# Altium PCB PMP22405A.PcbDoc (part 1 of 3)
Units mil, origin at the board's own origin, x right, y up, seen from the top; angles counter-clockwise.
Board outline 4300 x 4000 mil, 6 copper layers (Top Layer, Layer 2, Signal Layer 3, Signal Layer 4, Layer 5, Bottom Layer), stack 61.712 mil thick; 195 components, 65 nets, 472 pads, 772 vias.
Unrouted connection lines stored in the file: 12.
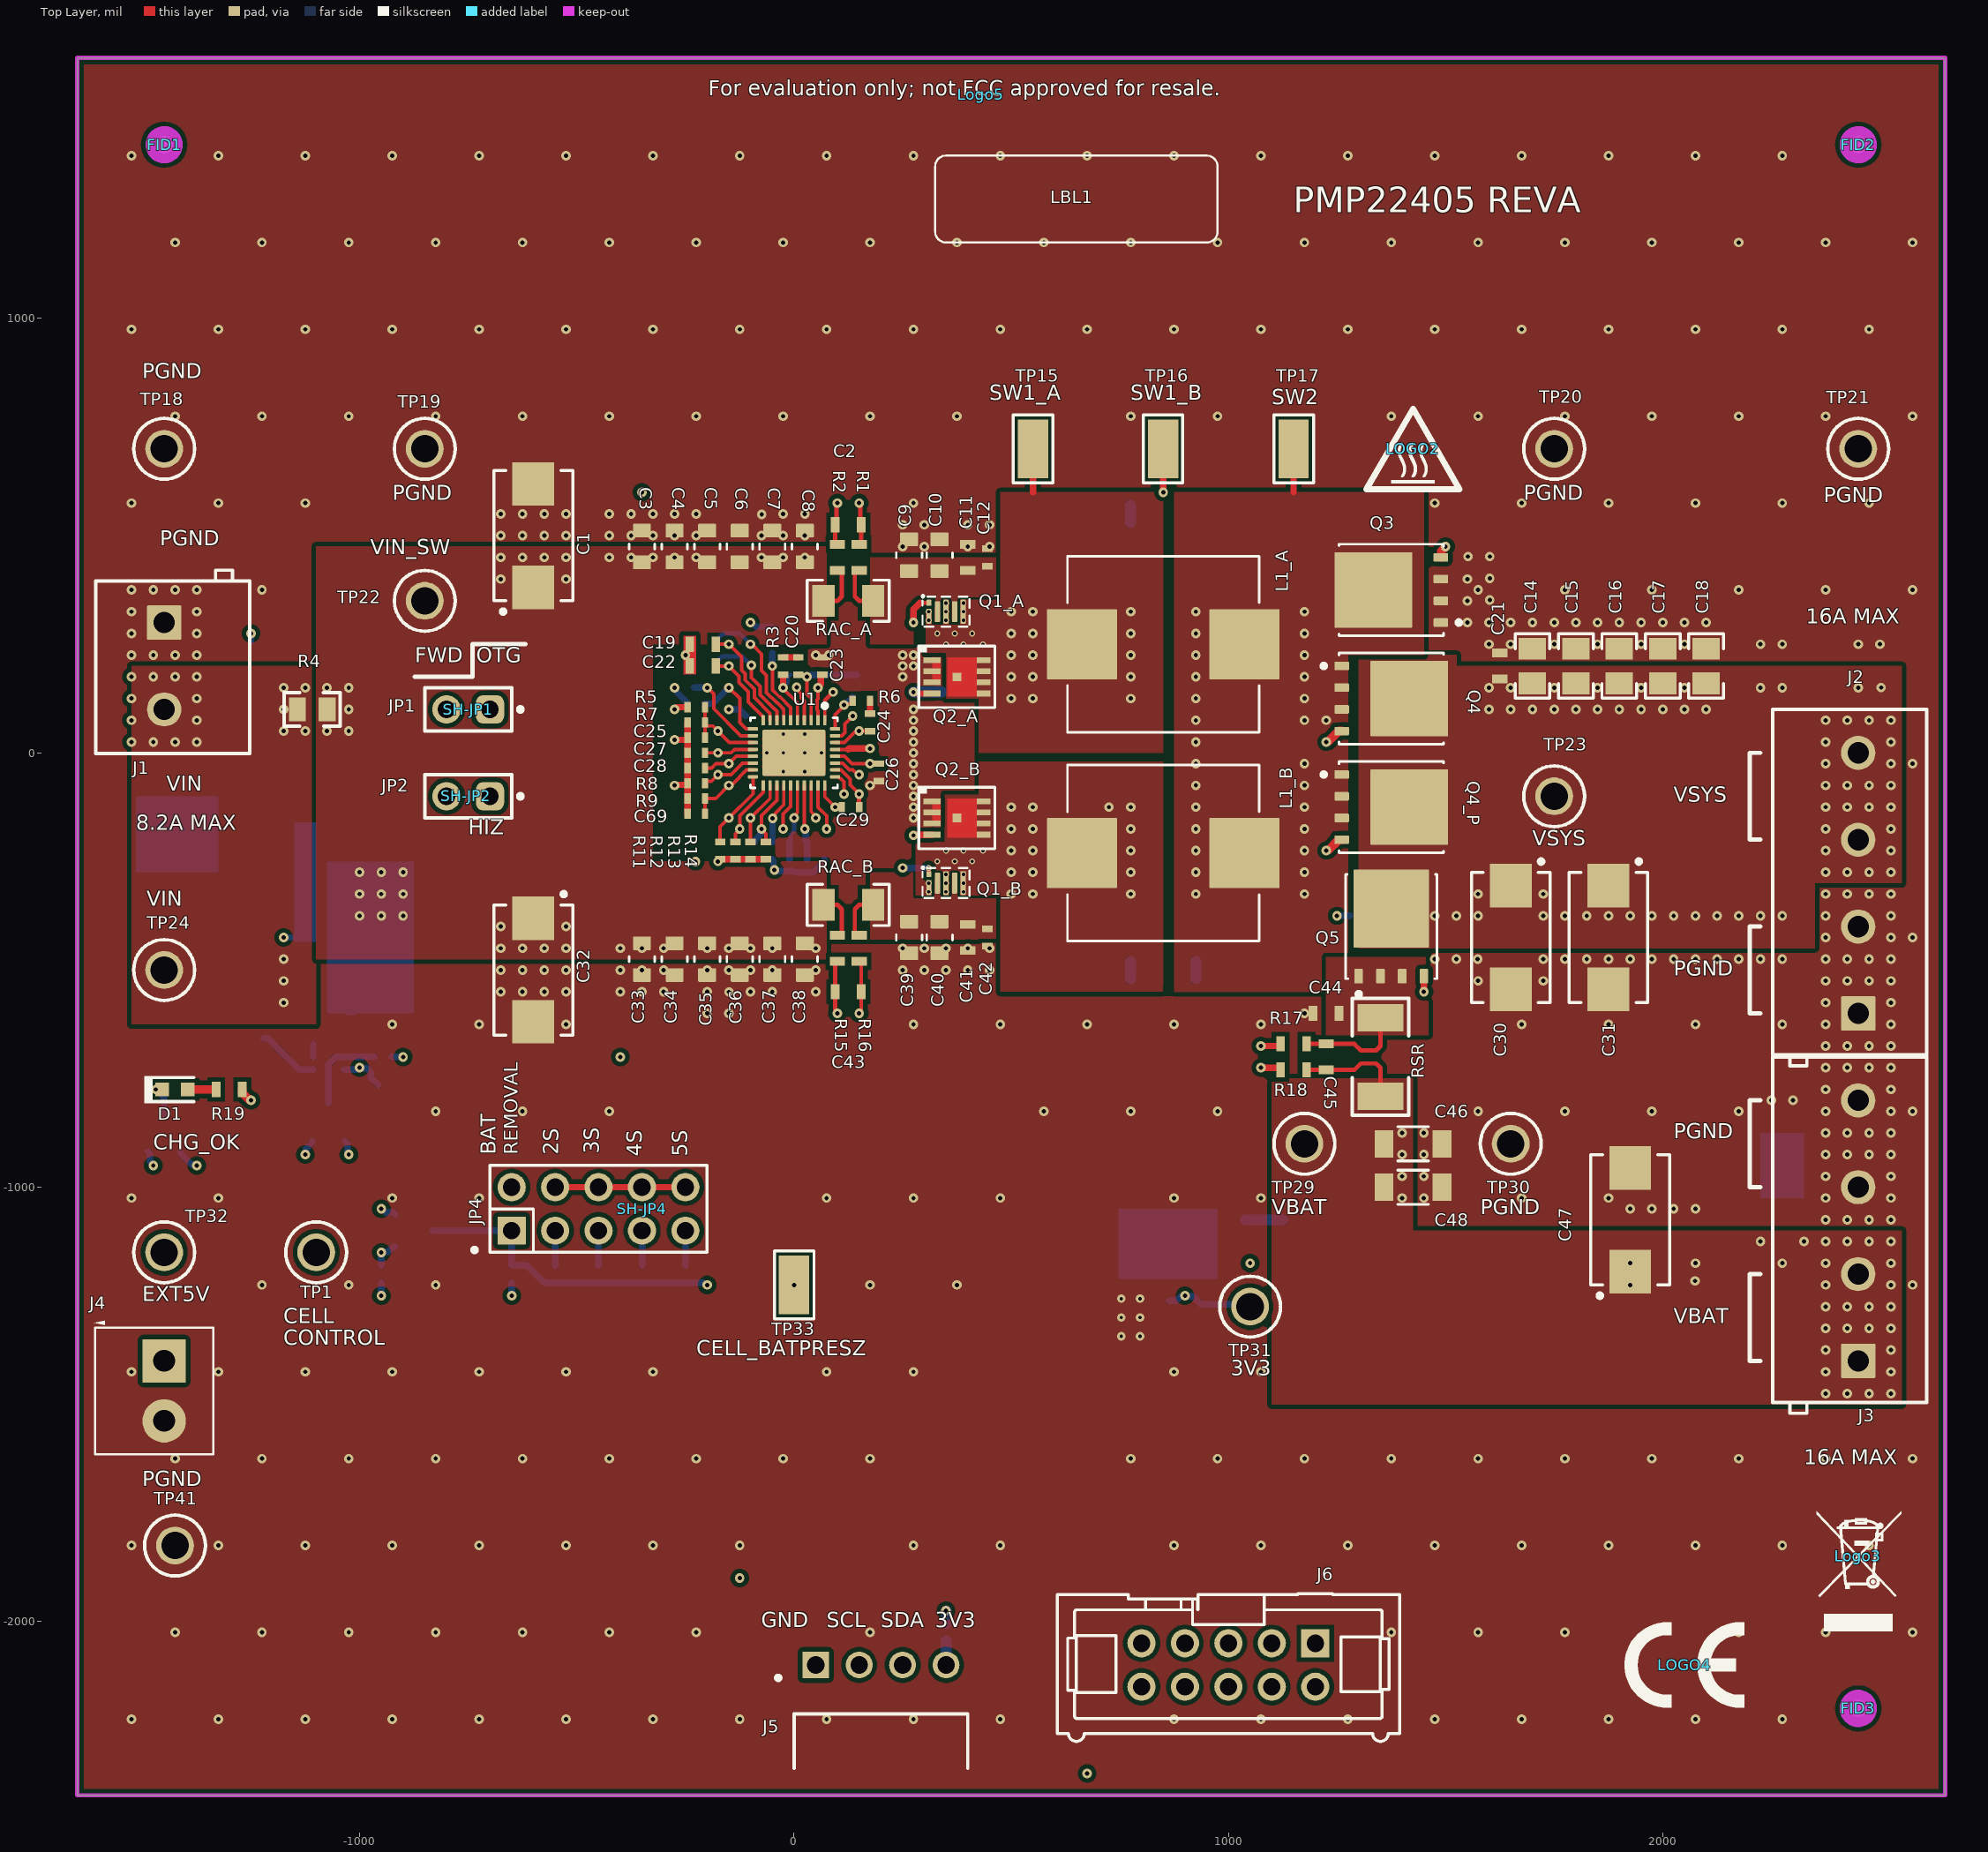
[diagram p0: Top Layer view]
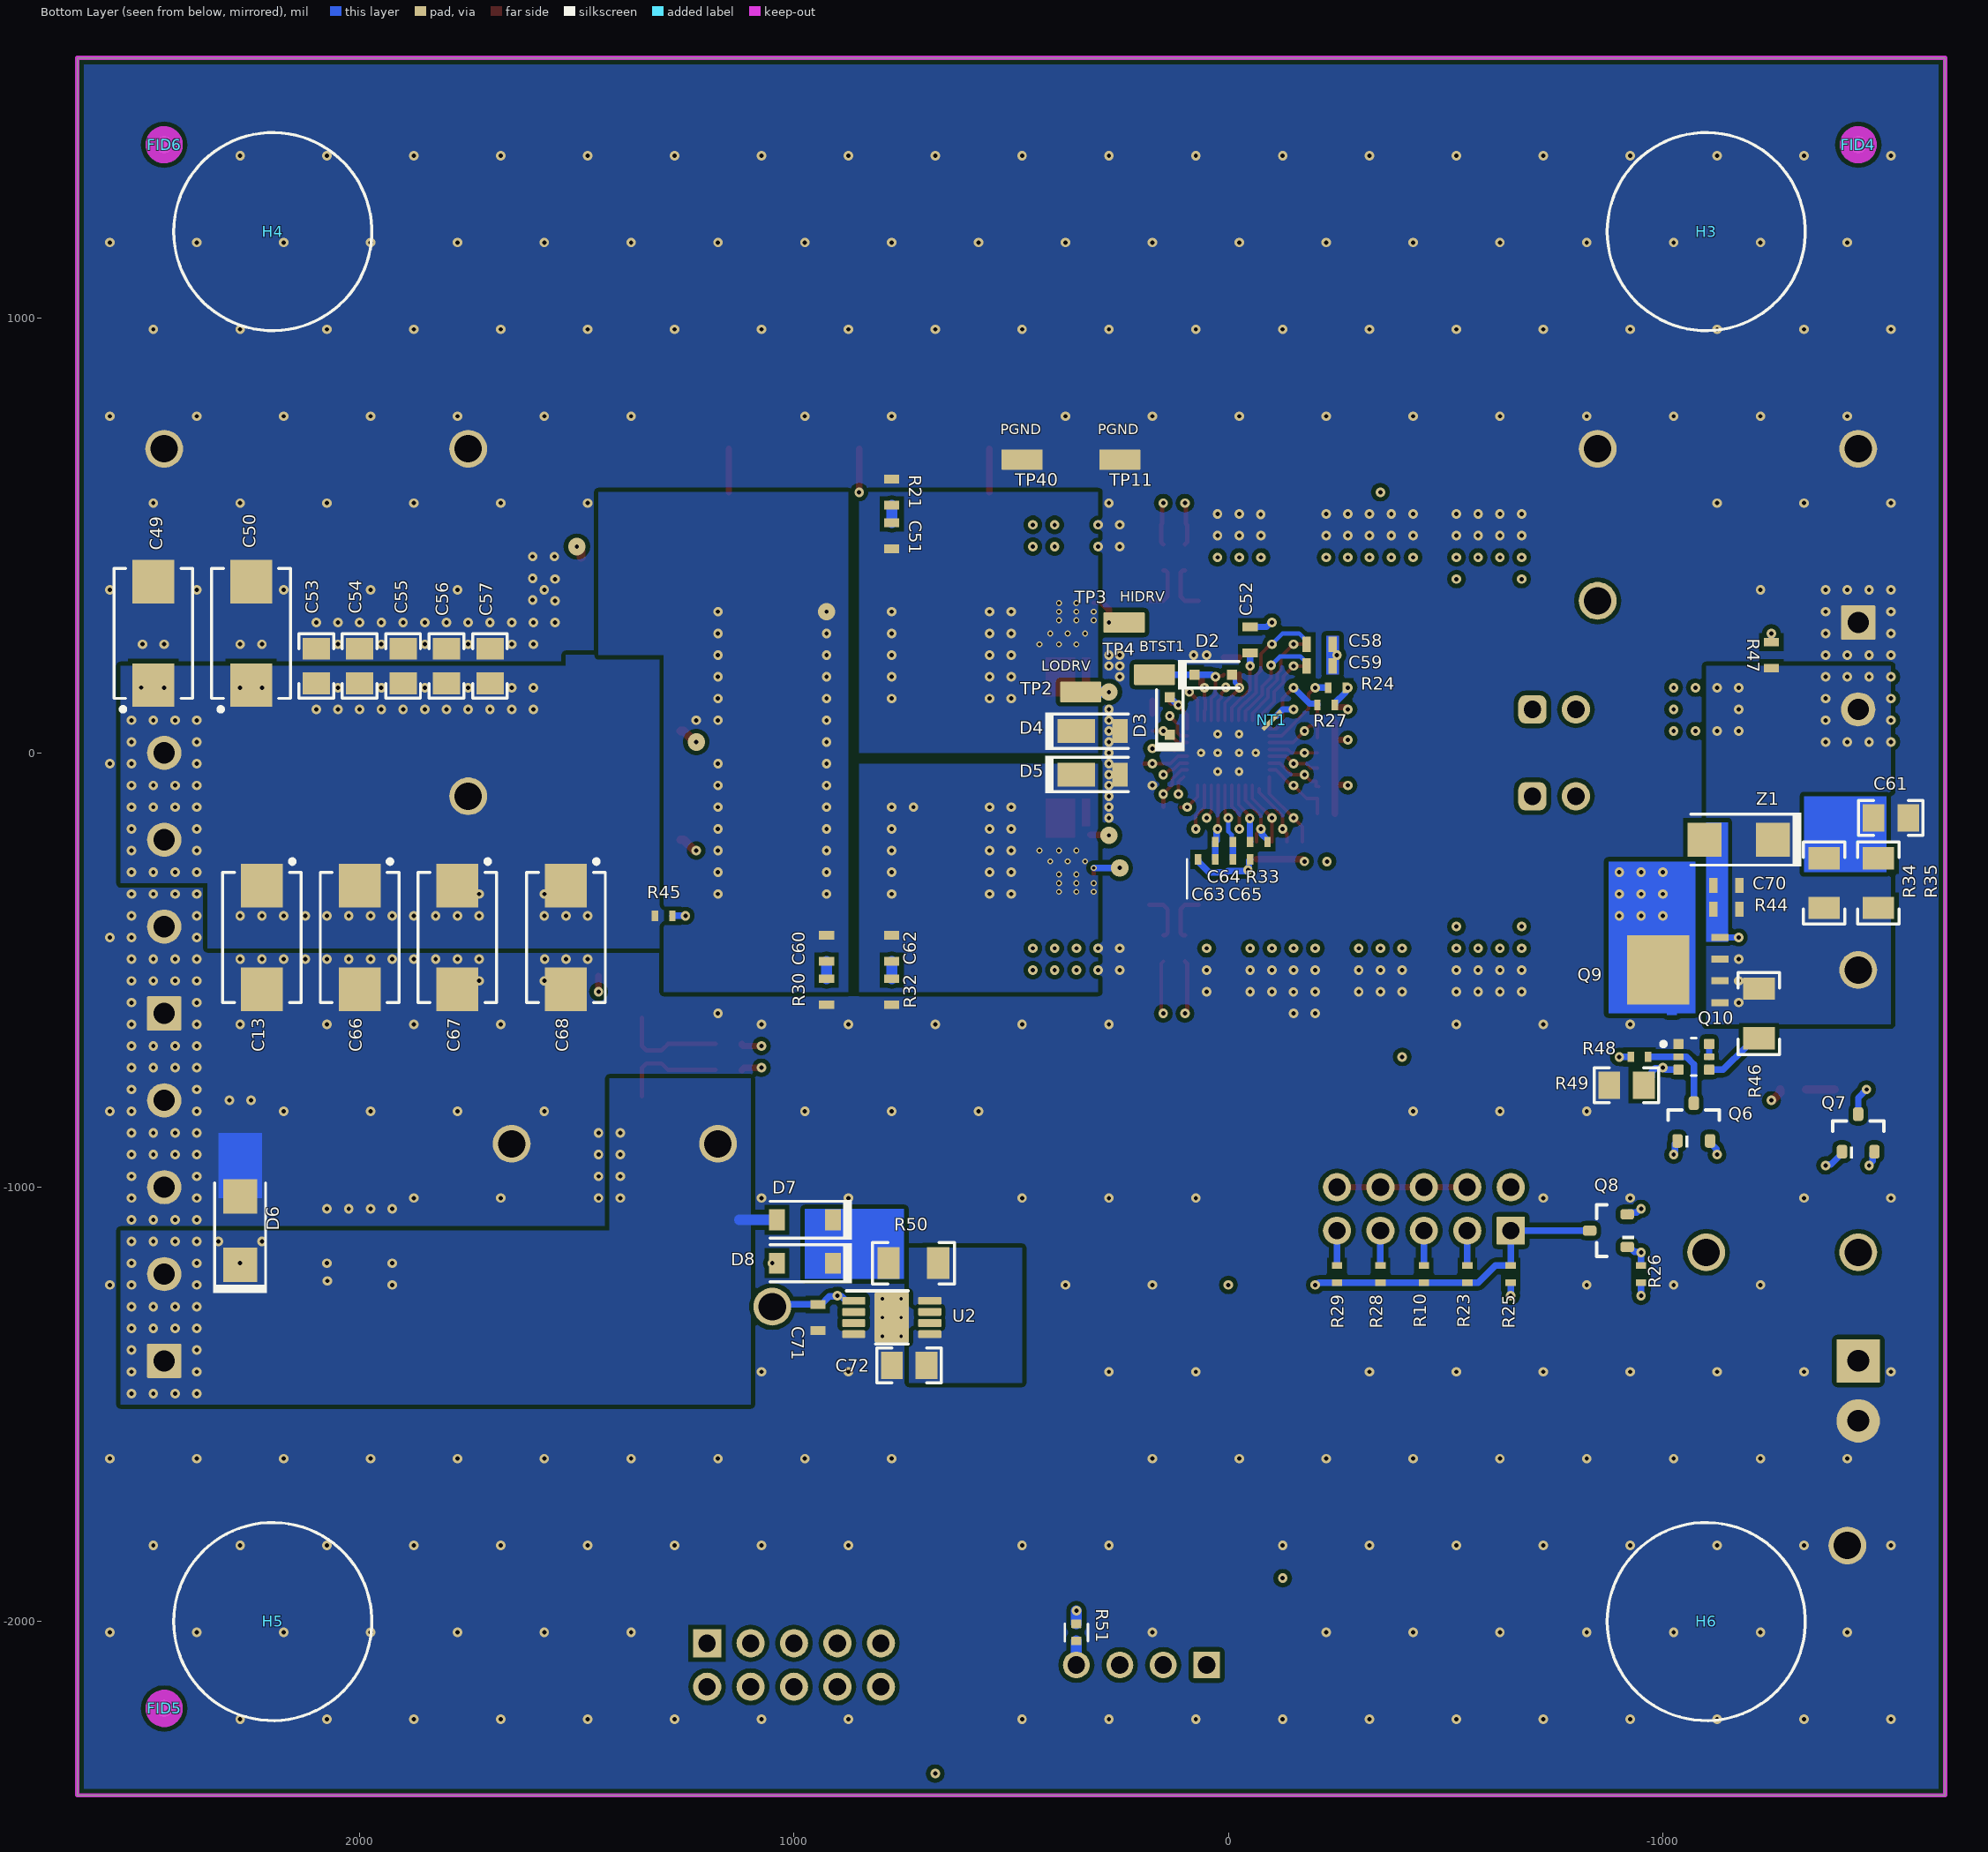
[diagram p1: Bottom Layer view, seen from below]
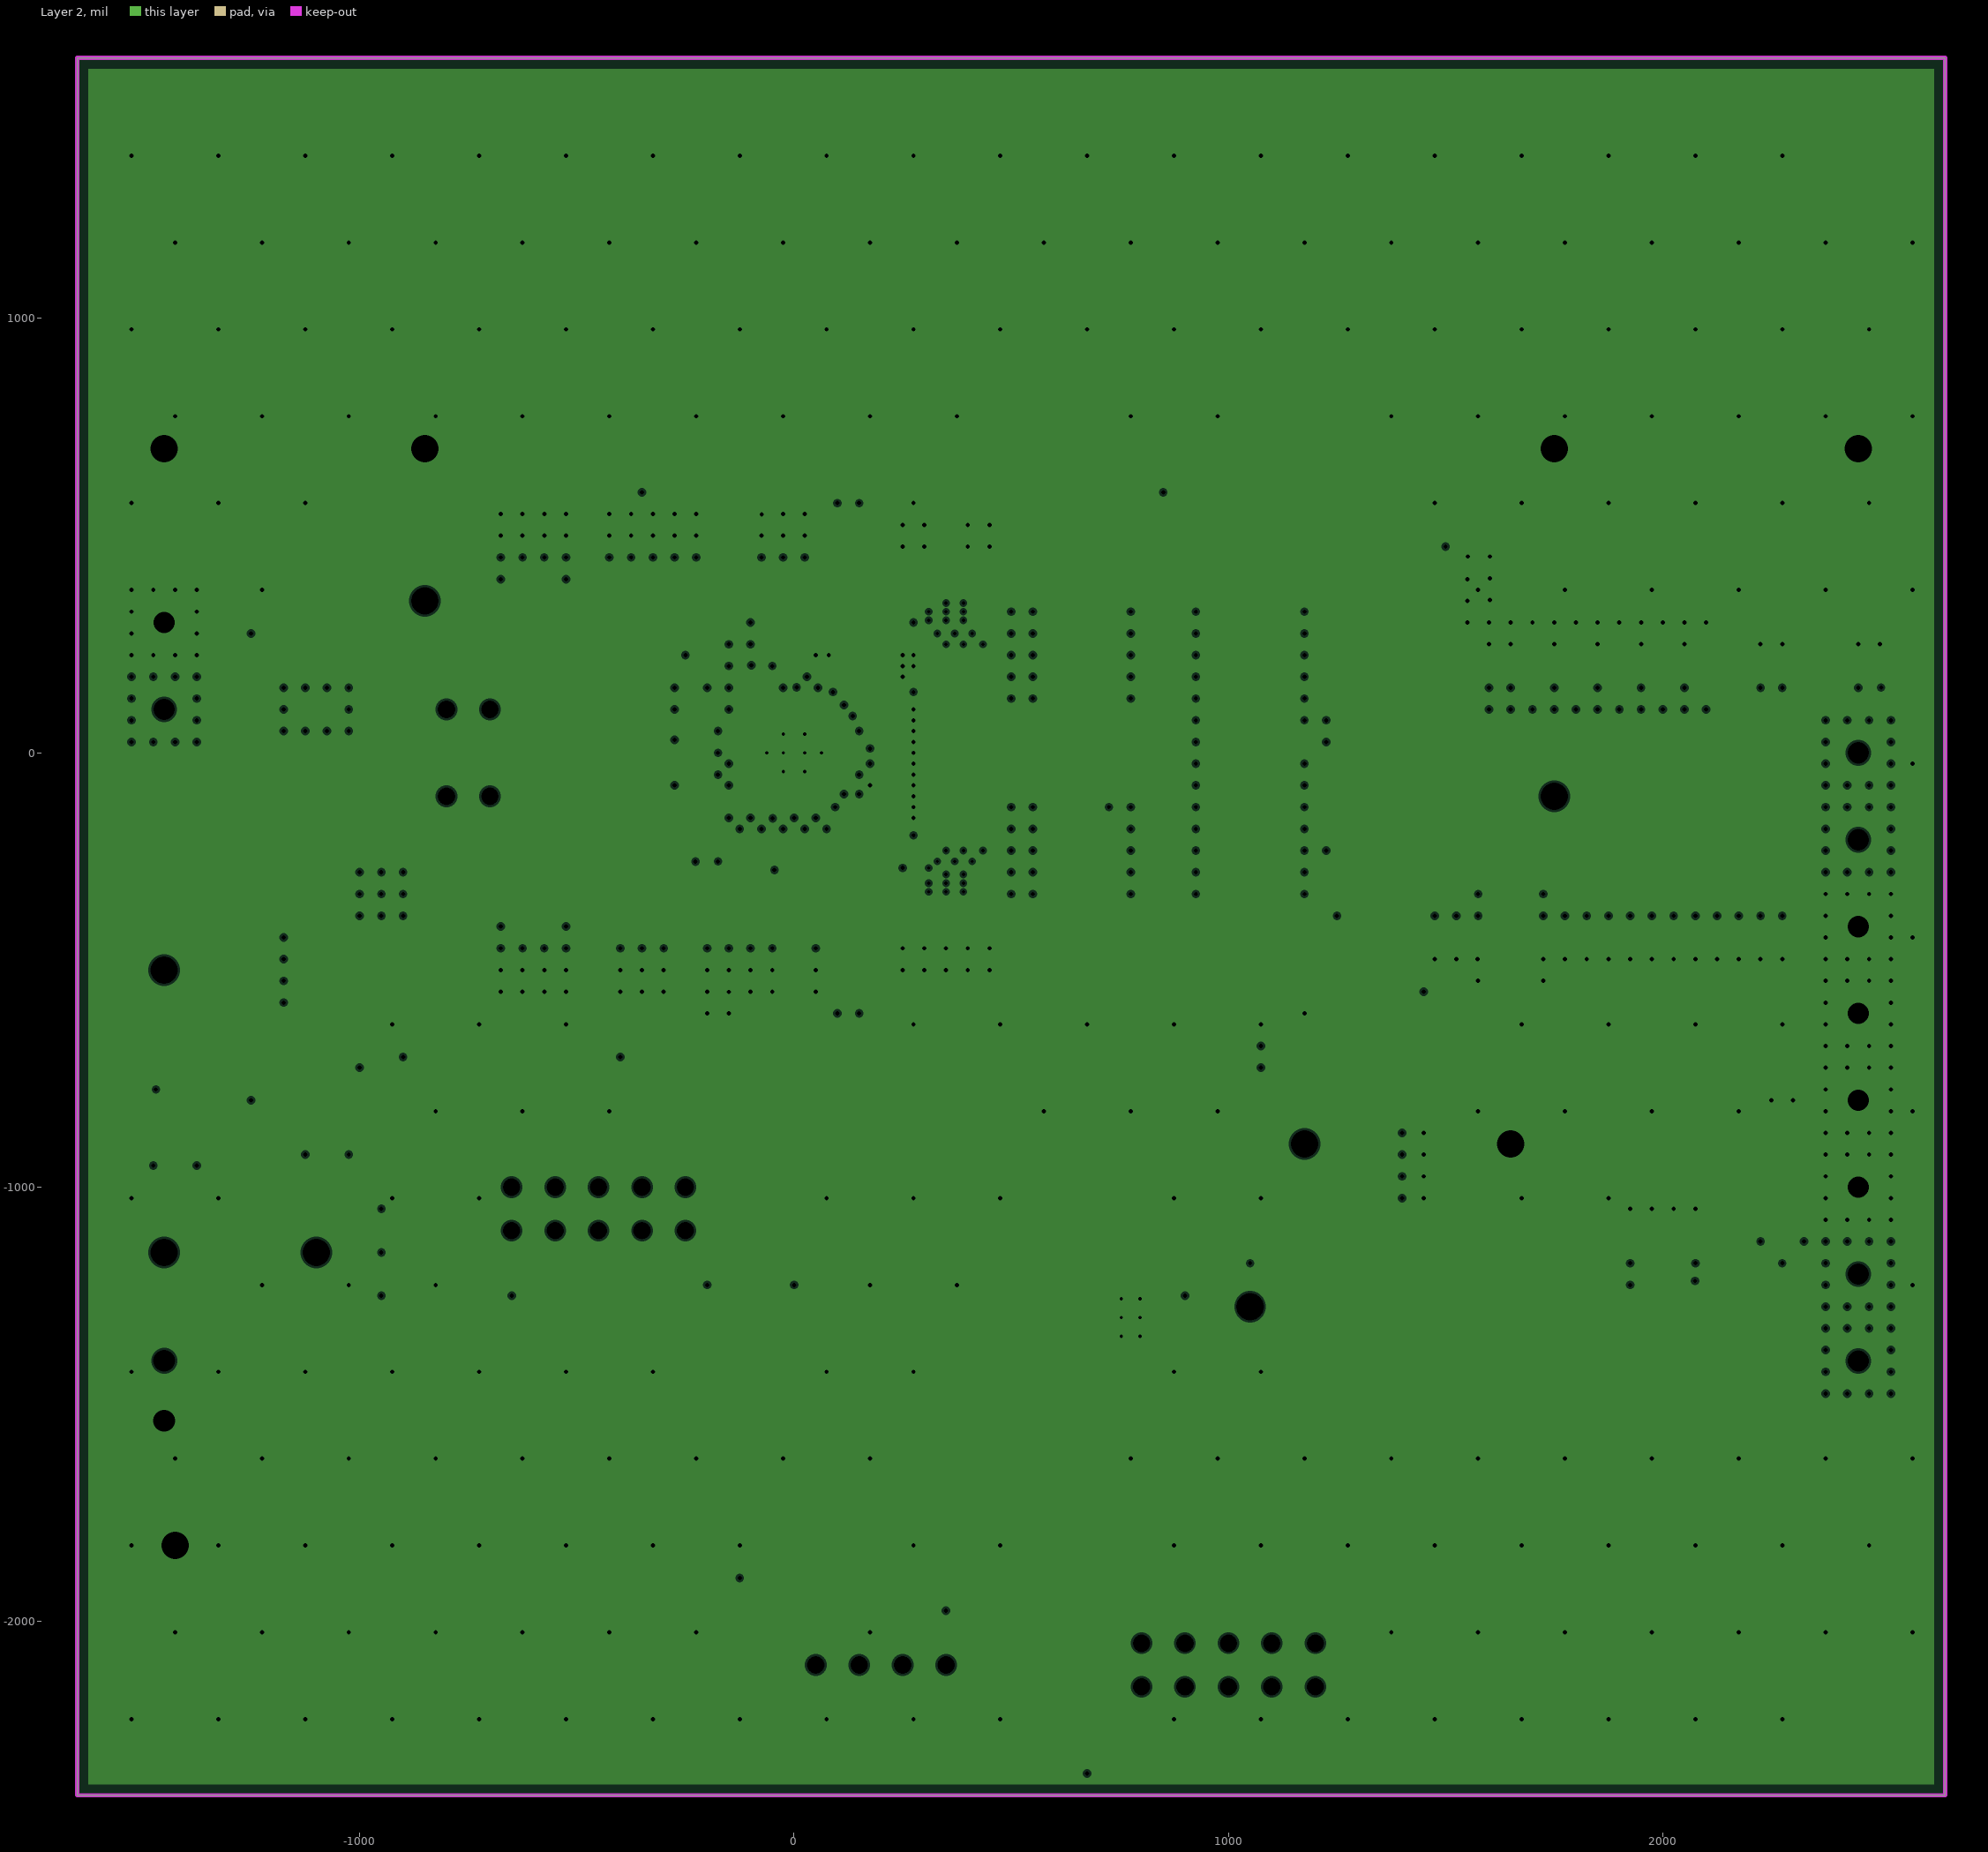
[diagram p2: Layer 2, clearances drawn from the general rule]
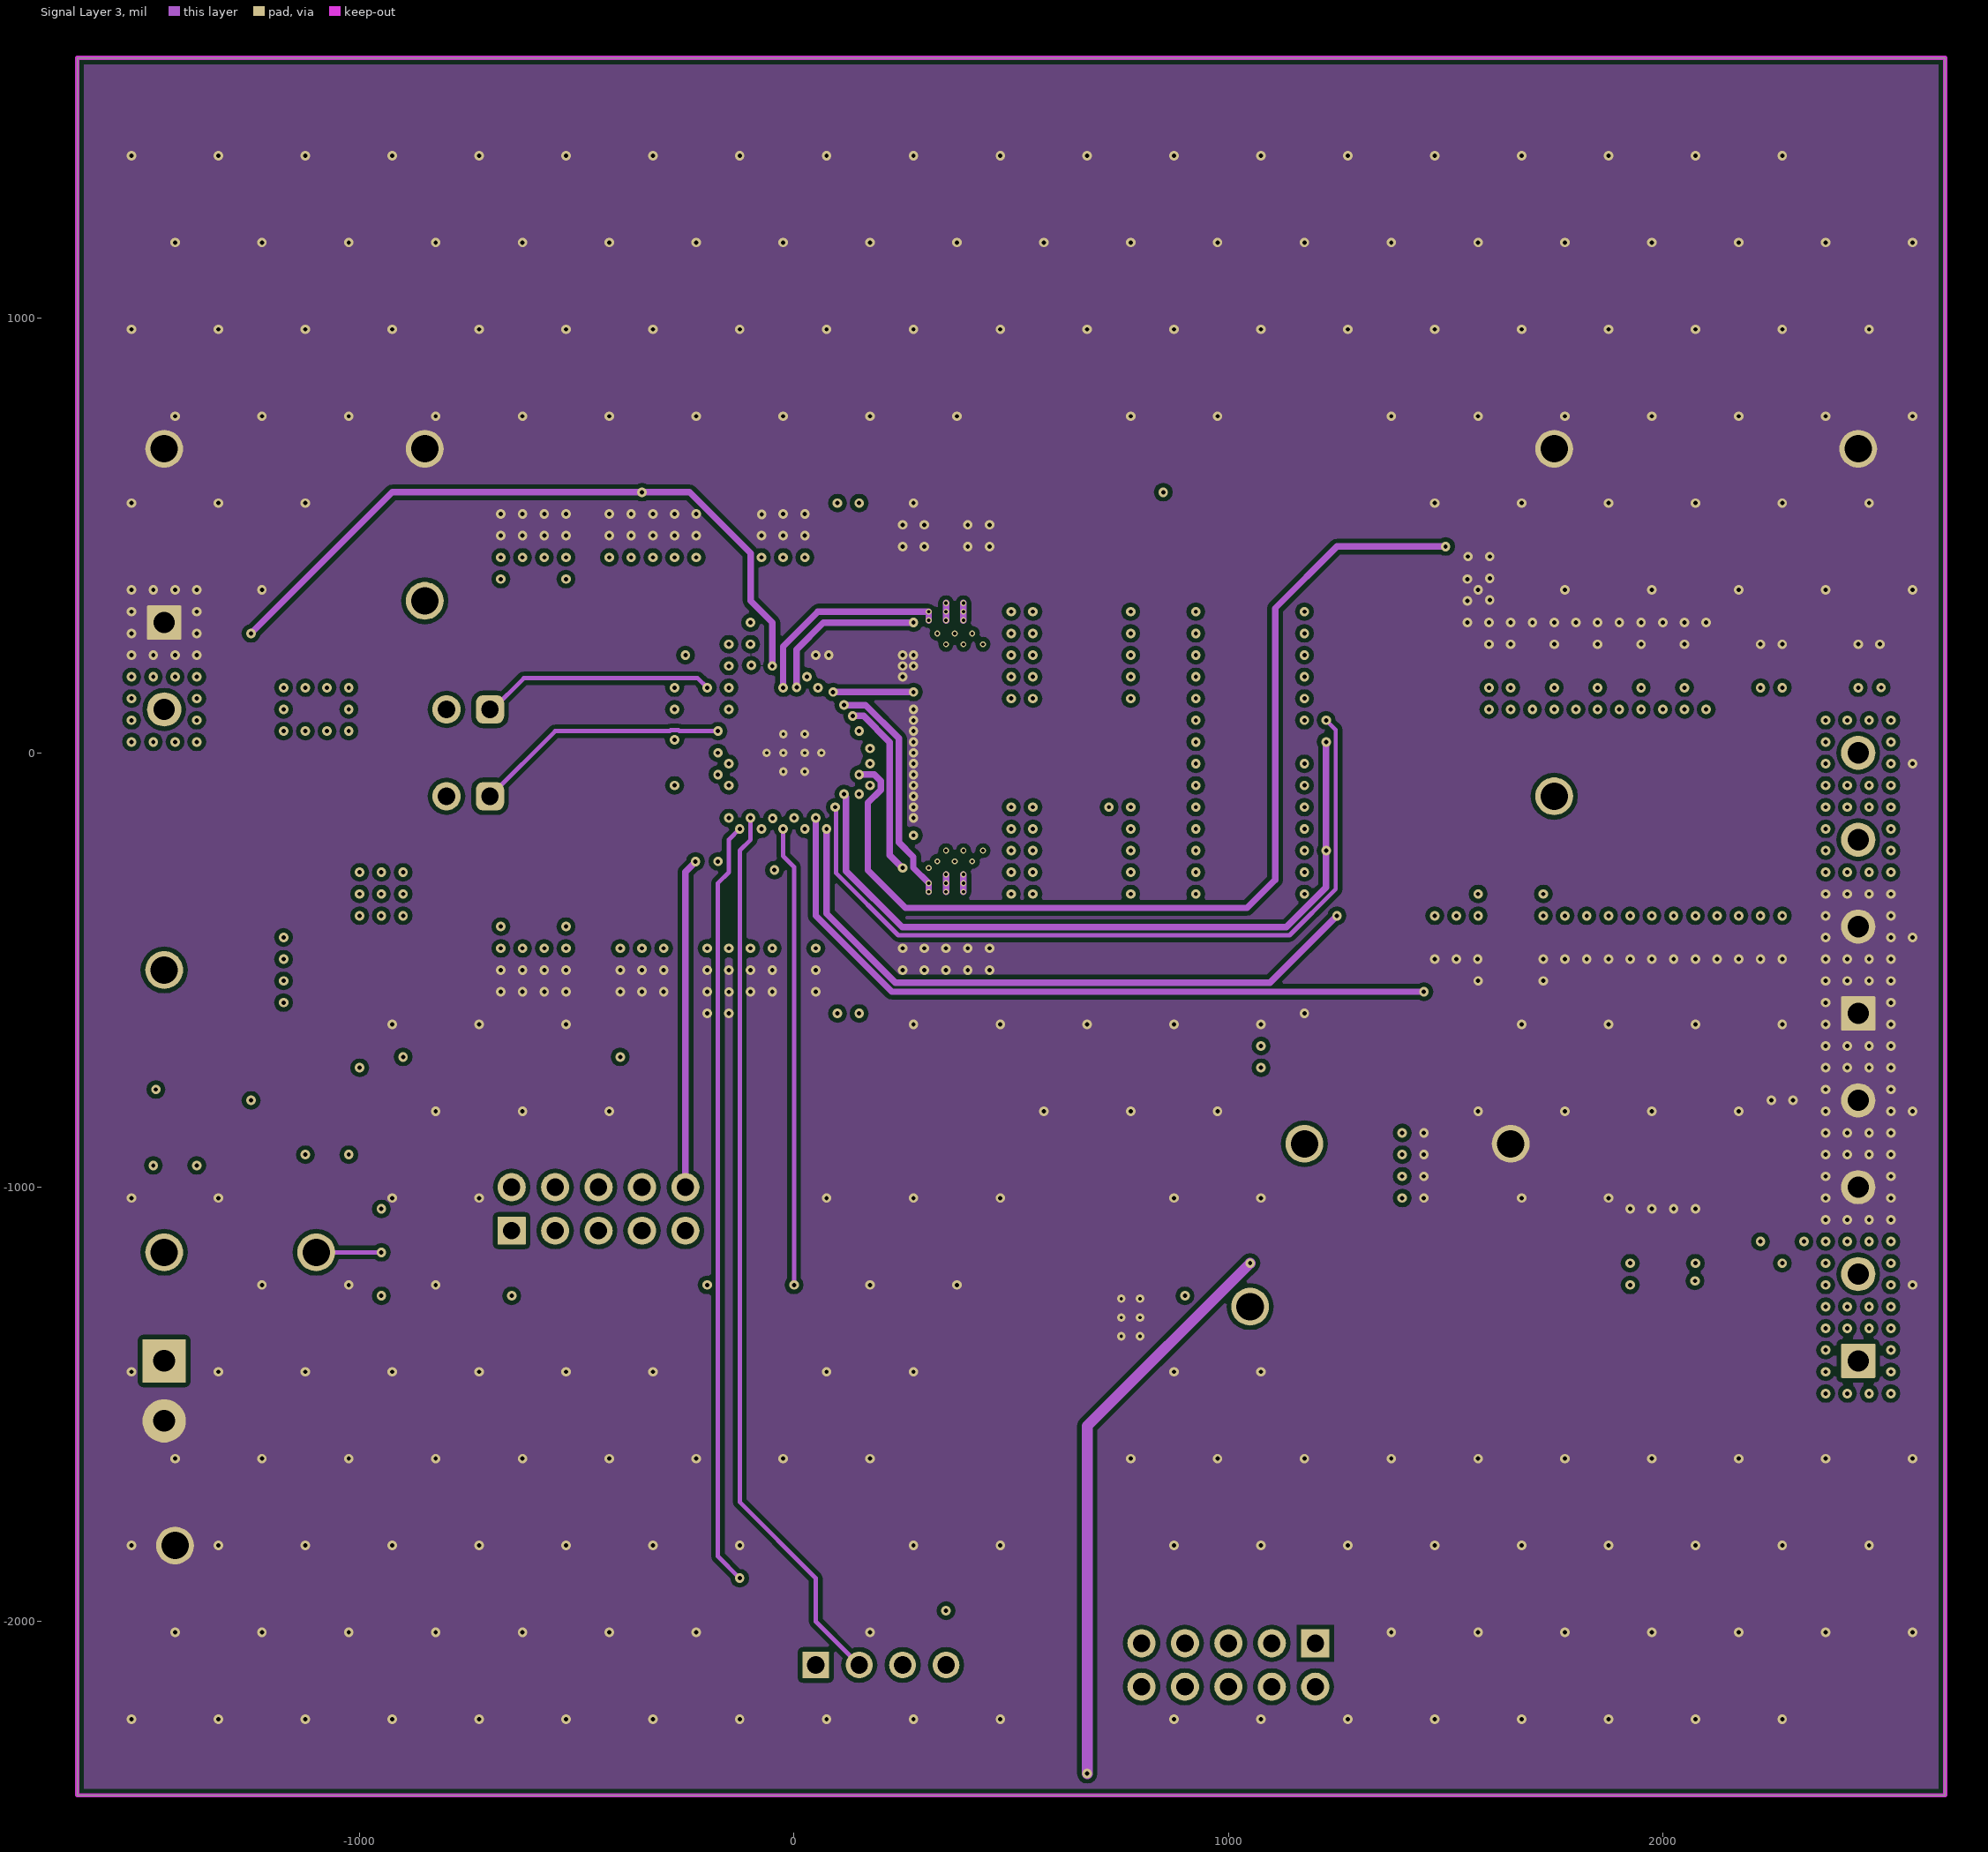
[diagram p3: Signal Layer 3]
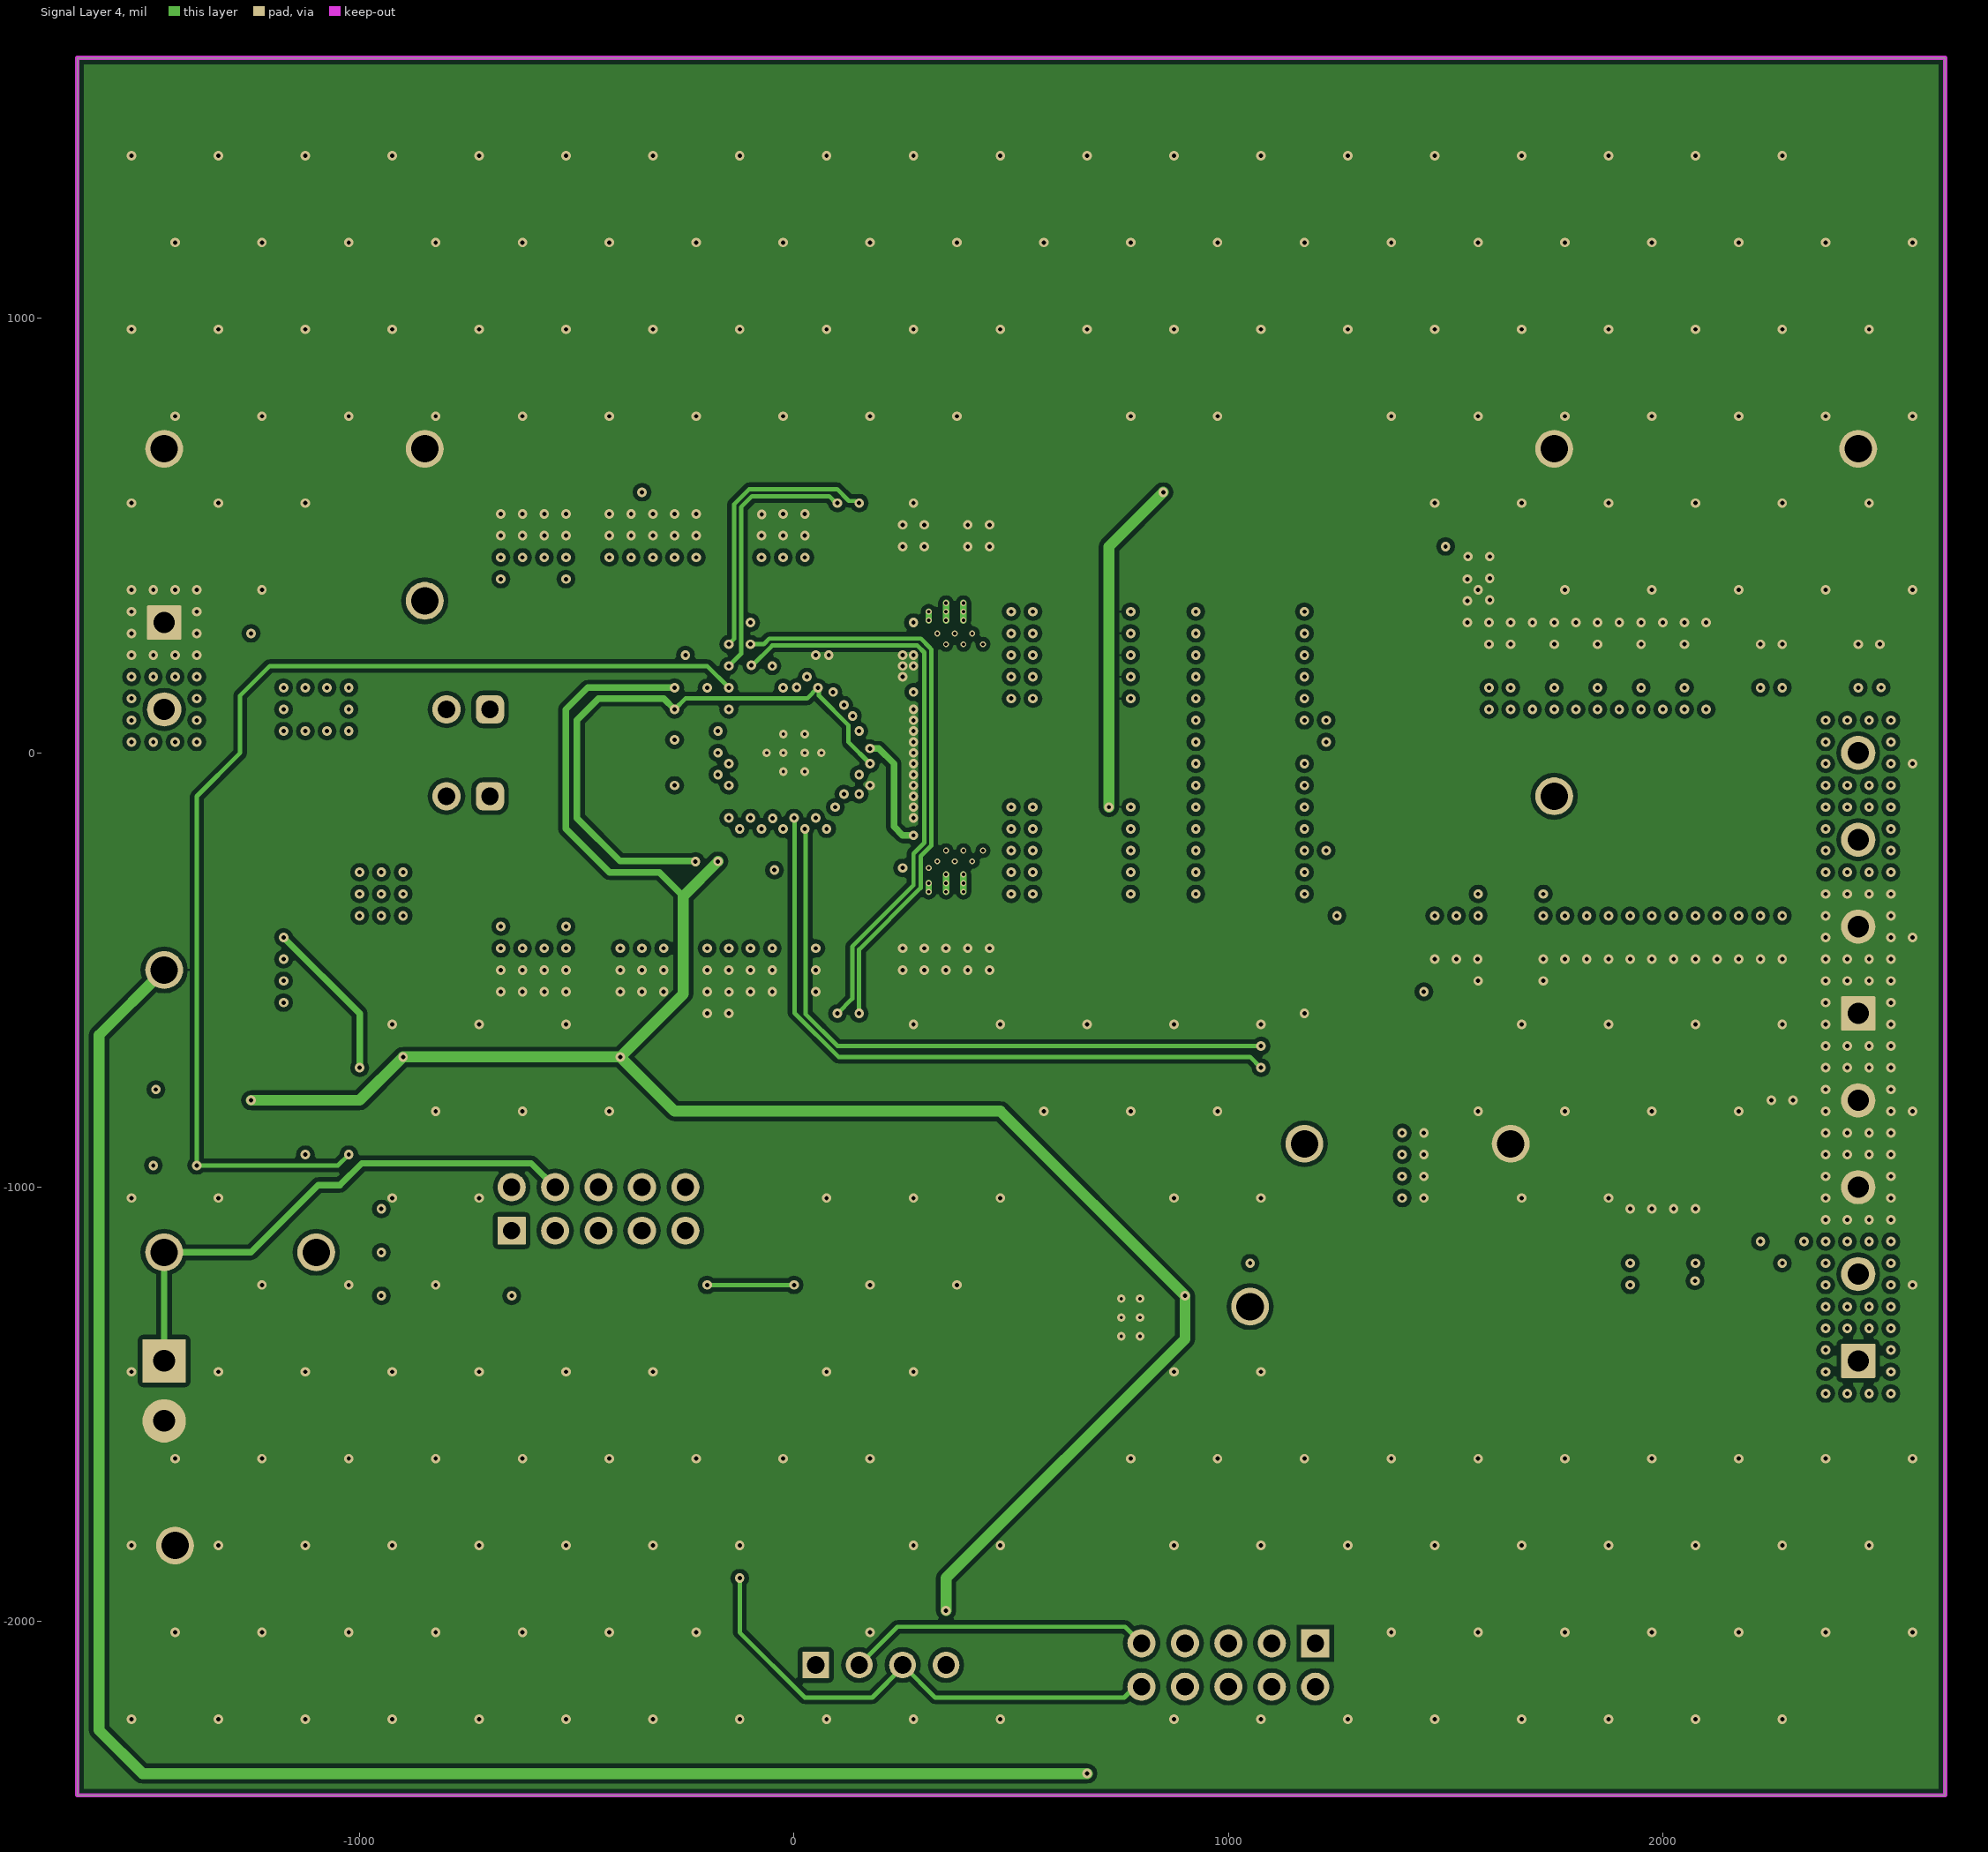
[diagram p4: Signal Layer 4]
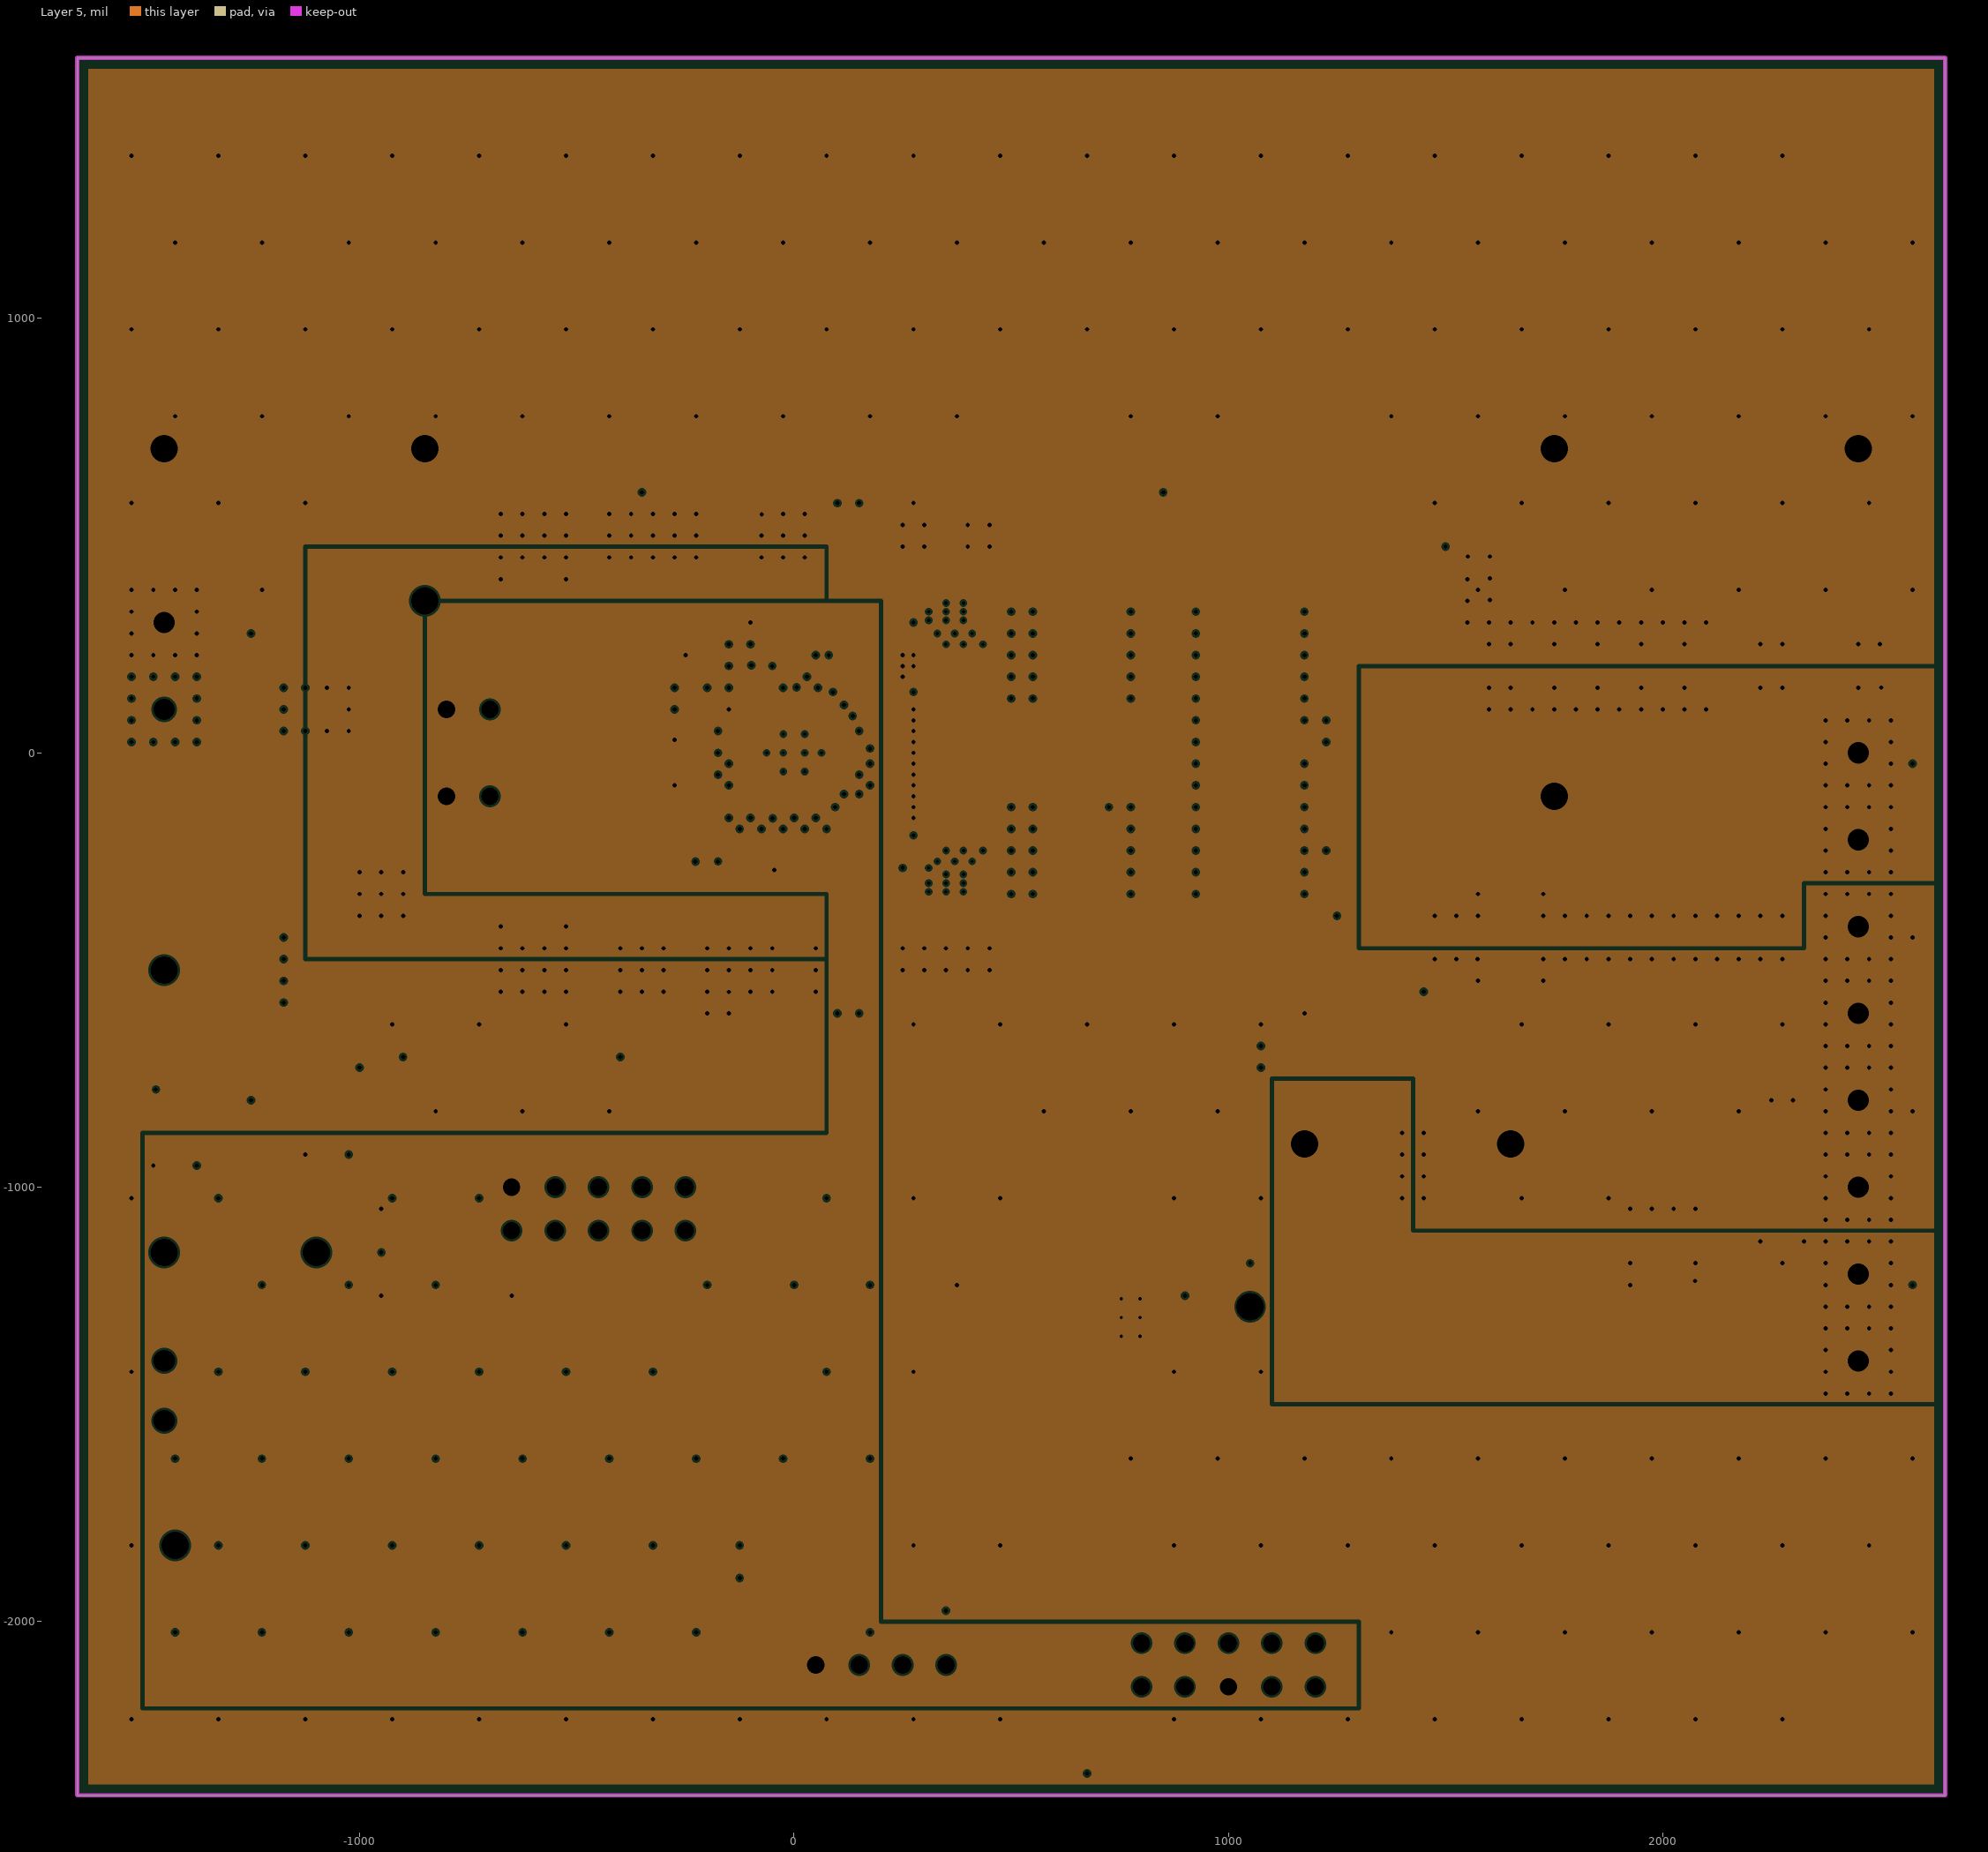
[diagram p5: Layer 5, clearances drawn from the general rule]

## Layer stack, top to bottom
Top Solder: solder mask 0.4, Solder Resist, Dk 3.5
Top Layer: signal copper 2.8
Dielectric1: core 5, FR-4 High TG, Dk 4.2
Layer 2: plane copper 2.756, net PGND
Dielectric 1: prepreg 5, PP-006, Dk 4.1
Signal Layer 3: signal copper 2.8
Dielectric 2: prepreg 25, FR-4 High TG, Dk 4.2
Signal Layer 4: signal copper 2.8
Dielectric 4: prepreg 5, PP-006, Dk 4.1
Layer 5: plane copper 2.756, net (Multiple Nets)
Dielectric 3: core 5, FR-4 High TG, Dk 4.2
Bottom Layer: signal copper 2.8
Bottom Solder: solder mask 0.4, Solder Resist, Dk 3.5

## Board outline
-1650,-2400 2650,-2400 2650,1600 -1650,1600

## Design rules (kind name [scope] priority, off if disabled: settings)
AcuteAngle [All] p1: minimum=4.50000000000000E+0001 checktracksonly=FALSE
AssemblyTestPointUsage [All] p1: valid=2
Clearance Clearance_HV_SW [InNetClass('HV') vs InNetClass('SWNODE')] p1 off: gap=10 ignorepadtopadclearanceinfootprint=TRUE
Clearance Clearance_SWNODE [InNetClass('SWNODE') vs InNetClass('LV')] p2 off: gap=10 ignorepadtopadclearanceinfootprint=TRUE
Clearance Clearance_HV [InNetClass('HV') vs InNetClass('LV')] p3 off: gap=10 ignorepadtopadclearanceinfootprint=TRUE
Clearance Clearance_FETs [(InNet('SW1_A') OR InNet('SW1_B')) vs (InNet('VIN_R_A') OR InNet('VIN_R_B'))] p4: gap=6 ignorepadtopadclearanceinfootprint=TRUE // For GAN FET
Clearance "Clearance_gnd polyd" [(InNet('GND') or InNet('PGND')) and inpoly] p5: gap=10 ignorepadtopadclearanceinfootprint=TRUE
Clearance Clearance_Keepouts [All vs IsKeepOut] p6: gap=25 ignorepadtopadclearanceinfootprint=FALSE
Clearance Clearance_BoardEdge_MountingHoles [OnCopper and InComponentClass('Mounting Holes') vs IsKeepOut] p7: gap=40 ignorepadtopadclearanceinfootprint=FALSE except(0: Arc-Hole Track-Hole SMDPad-Hole THPad-Hole Via-Hole Fill-Hole Poly-Hole Region-Hole Text-Hole)
Clearance Clearance_BoardEdge_Poly [OnCopper and InPoly vs IsKeepOut] p8: gap=25 ignorepadtopadclearanceinfootprint=FALSE
Clearance Clearance_BoardEdge [IsKeepOut] p9: gap=25 ignorepadtopadclearanceinfootprint=FALSE
Clearance Clearance_Poly [InPolygon] p10: gap=10 ignorepadtopadclearanceinfootprint=FALSE
Clearance [All] p11: gap=6 ignorepadtopadclearanceinfootprint=TRUE
ComponentClearance ComponentClearance_NT [incomponent('NT1') vs incomponent('U1')] p1: gap=0 collisioncheckmode=3 verticalgap=0 showdistances=FALSE
ComponentClearance ComponentClearance_MountingHoles_FiducialMarks [InComponentClass('Mounting Holes') vs InComponentClass('FiducialMark')] p2: gap=50 collisioncheckmode=3 verticalgap=10 showdistances=FALSE
ComponentClearance ComponentClearance_Shunt [InComponentClass('Header') vs InComponentClass('Shunt')] p3: gap=0 collisioncheckmode=3 verticalgap=0 showdistances=FALSE
ComponentClearance ComponentClearance_Logo [InComponentClass('Logo')] p4: gap=50 collisioncheckmode=3 verticalgap=10 showdistances=FALSE
ComponentClearance ComponentClearance_ScrewToNut [(HasFootprint('NY PMS 440 0025 PH')) vs (HasFootprint('Keystone_1902C'))] p5: gap=5 collisioncheckmode=3 verticalgap=10 showdistances=FALSE
ComponentClearance ComponentClearance_MountingHoles [InComponentClass('Mounting Holes')] p6: gap=100 collisioncheckmode=3 verticalgap=100000 showdistances=FALSE
ComponentClearance ComponentClearance_SmallPassives [HasFootprint('0201*') or HasFootprint('0402*') or HasFootprint('0508') or HasFootprint('0603*') or HasFootprint('0612') or HasFootprint('0805*') or HasFootprint('0815*') or HasFootprint('0830*') or HasFootprint('1206*') or HasFootprint('1210*') or HasFootprint('1808*') or HasFootprint('1812*') or HasFootprint('1825*') or HasFootprint('2010*') or HasFootprint('2220*') or HasFootprint('2225*') or HasFootprint('2512*') or HasFootprint('2728*') or HasFootprint('3518*') vs HasFootprint('0201*') or HasFootprint('0402*') or HasFootprint('0508') or HasFootprint('0603*') or HasFootprint('0612') or HasFootprint('0805*') or HasFootprint('0815*') or HasFootprint('0830*') or HasFootprint('1206*') or HasFootprint('1210*') or HasFootprint('1808*') or HasFootprint('1812*') or HasFootprint('1825*') or HasFootprint('2010*') or HasFootprint('2220*') or HasFootprint('2225*') or HasFootprint('2512*') or HasFootprint('2728*') or HasFootprint('3518*')] p7: gap=10 collisioncheckmode=3 verticalgap=10 showdistances=FALSE
ComponentClearance ComponentClearance_THtoSMT [IsThruComponent vs IsSMTComponent] p8: gap=30 collisioncheckmode=3 verticalgap=30 showdistances=FALSE
ComponentClearance ComponentClearance_THtoTH [IsThruComponent vs IsThruComponent] p9: gap=30 collisioncheckmode=3 verticalgap=30 showdistances=FALSE
ComponentClearance [All] p10: gap=20 collisioncheckmode=3 verticalgap=10 showdistances=FALSE
DiffPairsRouting [All] p1: maxlimit=100 minlimit=10 mostfreqgap=10 toplayer_minwidth=10 toplayer_maxwidth=15 toplayer_prefwidth=10 midlayer1_minwidth=10 midlayer1_maxwidth=15 midlayer1_prefwidth=10 midlayer2_minwidth=10 midlayer2_maxwidth=15 midlayer2_prefwidth=10 bottomlayer_minwidth=10 bottomlayer_maxwidth=15 bottomlayer_prefwidth=10 maxuncoupledlength=1000
FabricationTestPointUsage TestPointUsage [All] p1: valid=2 allowmultiple=FALSE
FabricationTestpoint Testpoint [All] p1: side=3 testpointundercomponent=TRUE minsize=40 maxsize=100 preferedsize=60 minholesize=0 maxholesize=40 preferedholesize=32 testpointgrid=1 allowsidetop=TRUE allowsidebottom=TRUE usegrid=TRUE gridtolerance=0.01
FanoutControl Fanout_LCC [IsLCC] p1: bgadir=Out bgaviamode=Centered fanoutstyle=Auto fanoutdirection=Alternating viagrid=1 // Fanout_LCC (Default Rule)
FanoutControl Fanout_BGA [IsBGA] p2: bgadir=Out bgaviamode=Centered fanoutstyle=Auto fanoutdirection=Alternating viagrid=1 // Fanout_BGA (Default Rule)
HoleSize [All] p1: absolutevalues=TRUE maxlimit=251 minlimit=5.9 maxpercent=80.000 minpercent=20.000
MinimumAnnularRing MinimumAnnularRing_ThermalPadVias [IsVia and InAnyComponent] p1: minimumring=3
MinimumAnnularRing [All] p2: minimumring=3
MinimumSolderMaskSliver MinimumSolderMaskSliver_Logo [InComponentClass('Logo') vs InComponentClass('Logo')] p1: minsoldermaskwidth=0.7
MinimumSolderMaskSliver [All] p2: minsoldermaskwidth=3.94
PlaneClearance [All] p1: clearance=5
PlaneConnect [All] p1: planeconnectstyle=Direct reliefexpansion=10 reliefentries=4 reliefconductorwidth=10 reliefairgap=10
PolygonConnect [All] p1: connectstyle=Direct reliefconductorwidth=10 reliefentries=4 polygonreliefangle="90 Angle" airgapwidth=10
RoutingVias ThermalPadVias [IsVia and InAnyComponent] p1: holewidth=7.87 width=19.68 viastyle="Through Hole" minholewidth=7.87 minwidth=19.68 maxholewidth=12.99 maxwidth=23.62
RoutingVias [All] p2: holewidth=10 width=22 viastyle="Through Hole" minholewidth=5.9 minwidth=9.9 maxholewidth=40 maxwidth=65
SilkToSilkClearance SilkToSilkClearance_Pb-FreeLogo [(HasFootprint('Pb-Free_Overlay_Medium') OR HasFootprint('Pb-Free_Overlay_Small')) vs (HasFootprint('Pb-Free_Overlay_Medium') OR HasFootprint('Pb-Free_Overlay_Small'))] p1: silktosilkclearance=0
SilkToSilkClearance [All] p2: silktosilkclearance=3
SilkToSolderMaskClearance "SilkToSolderMaskClearance FETS" [all vs hasfootprint('TRANS_NexFET_Q3A')] p1: minsilkscreentomaskgap=0.5 clearancetoexposedcopper=FALSE
SilkToSolderMaskClearance "Silk to Solder Mask Opening" [All] p2: minsilkscreentomaskgap=3 clearancetoexposedcopper=FALSE
SolderMaskExpansion [All] p1: expansion=1.97 istentingtop=FALSE
Width [All] p1: maxlimit=100 minlimit=8 preferedwidth=10
17 further rules are at their usual default settings.

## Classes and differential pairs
net class SWNODE: BTST1_A BTST1_B BTST2 HIDRV1_A HIDRV1_B HIDRV2 SW1_A SW1_B SW2 VBAT_R
net class LV: 3V3 CELL_BATPRESZ CELL_CONTROL CHRG_OK CMPIN_TR CMPOUT EN_OTG GND IADPT IBAT ILIM_HIZ LODRV1_A LODRV1_B LODRV2 MODE NetC20_2 NetC24_2 NetC51_2 NetC60_2 NetC61_1 NetC62_2 NetC70_1 NetC72_2 NetD1_1 NetD1_2 NetD7_1 NetJ5_4 NetJP4_3 NetJP4_5 NetJP4_7 NetJP4_9 NetQ6_3 NetQ10_4 NetQ10_5 PGND PROCHOT PSYS REGN SCL SDA
net class HV: ACN_A ACN_B ACP_A ACP_B BTST1_A BTST1_B BTST2 HIDRV1_A HIDRV1_B HIDRV2 SRN SRP SW1_A SW1_B SW2 VBAT VBAT_R VBUS VIN VIN_R_A VIN_R_B VIN_SW VSYS VSYS_P
component class BMS089REVA_Hardware: FID1 FID2 FID3 FID4 FID5 FID6 H3 H4 H5 H6 LBL1 LOGO2 Logo3 LOGO4 Logo5 SH-JP1 SH-JP2 SH-JP4 TP2 TP3 TP4 TP11 TP33 TP40 ZZ1 ZZ2 ZZ3 ZZ4
component class FiducialMark: FID1 FID2 FID3 FID4 FID5 FID6
component class AssemblyNote: ZZ1 ZZ2 ZZ3 ZZ4
component class Label: LBL1
component class BMS089REVA: C1 C2 C3 C4 C5 C6 C7 C8 C9 C10 C11 C12 C13 C14 C15 C16 C17 C18 C19 C20 C21 C22 C23 C24 C25 C26 C27 C28 C29 C30 C31 C32 C33 C34 C35 C36 C37 C38 C39 C40 C41 C42 C43 C44 C45 C46 C47 C48 C49 C50 C51 C52 C53 C54 C55 C56 C57 C58 C59 C60 C61 C62 C63 C64 C65 C66 C67 C68 C69 C70 C71 C72 D1 D2 D3 D4 D5 D6 D7 D8 J1 J2 J3 J4 J5 J6 JP1 JP2 JP4 L1_A L1_B NT1 Q1_A Q1_B Q2_A Q2_B Q3 Q4 Q4_P Q5 Q6 Q7 Q8 Q9 Q10 R1 R2 R3 R4 R5 R6 R7 R8 R9 R10 R11 R12 R13 R14 R15 R16 R17 R18 R19 R21 R23 R24 R25 R26 R27 R28 R29 R30 R32 R33 R34 R35 R44 R45 R46 R47 R48 R49 R50 R51 RAC_A RAC_B RSR TP1 TP15 TP16 TP17 TP18 TP19 TP20 TP21 TP22 TP23 TP24 TP29 TP30 TP31 TP32 TP41 U1 U2 Z1
component class Header: JP1 JP2 JP4
component class Shunt: SH-JP1 SH-JP2 SH-JP4

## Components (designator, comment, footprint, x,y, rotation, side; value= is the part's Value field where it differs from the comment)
C1 "TR3E106K063C0600" 7343-43 -600,500 r90 top value=10uF
C2 "CGA3E2X7R1H104K080AA" 0603S 125,525 r0 top value=0.1uF
C3 "C2012X5R2A475K125AC" FP-C2012X5R2A475K125AC_0805-MFG -350,475 r270 top value=4.7µF
C4 "C2012X5R2A475K125AC" FP-C2012X5R2A475K125AC_0805-MFG -275,475 r270 top value=4.7µF
C5 "C2012X5R2A475K125AC" FP-C2012X5R2A475K125AC_0805-MFG -200,475 r270 top value=4.7µF
C6 "C2012X5R2A475K125AC" FP-C2012X5R2A475K125AC_0805-MFG -125,475 r270 top value=4.7µF
C7 "C2012X5R2A475K125AC" FP-C2012X5R2A475K125AC_0805-MFG -50,475 r270 top value=4.7µF
C8 "C2012X5R2A475K125AC" FP-C2012X5R2A475K125AC_0805-MFG 25,475 r270 top value=4.7µF
C9 "C2012X5R2A475K125AC" FP-C2012X5R2A475K125AC_0805-MFG 265,455 r270 top value=4.7µF
C10 "C2012X5R2A475K125AC" FP-C2012X5R2A475K125AC_0805-MFG 335,455 r270 top value=4.7µF
C11 "C0603C103J1RACTU" 0603S 400,450 r90 top value=0.01uF
C12 "GRM155R72A102KA01D" 0402S 445,450 r90 top value=1000pF
C13 "T521X336M050ATE050" 7343-43 2225,-425 r270 bottom value=33uF
C14 "C2012JB1V106K125AC" 0805_HV 1700,200 r90 top value=10uF
C15 "C2012JB1V106K125AC" 0805_HV 1800,200 r90 top value=10uF
C16 "C2012JB1V106K125AC" 0805_HV 1900,200 r90 top value=10uF
C17 "C2012JB1V106K125AC" 0805_HV 2000,200 r90 top value=10uF
C18 "C2012JB1V106K125AC" 0805_HV 2100,200 r90 top value=10uF
C19 "CGA3E3X7S2A333K080AB" 0603S -210,250 r180 top value=0.033uF
C20 "CGA2B3X7R1E104K050BB" 0402S 10,200 r90 top value=0.1uF
C21 "C0603C103J1RACTU" 0603S 1625,200 r90 top value=0.01uF
C22 "CGA3E3X7S2A333K080AB" 0603S -210,200 r180 top value=0.033uF
C23 "GRM155R61E225ME15D" 0402S 65,200 r90 top value=2.2uF
C24 "CGA2B3X7R1E104K050BB" 0402S 175,70 r90 top value=0.1uF
C25 "GRM1555C1H101JA01D" 0402S -225,35 r180 top value=100pF
C26 "GRM155R61E225ME15D" 0402S 195,-45 r90 top value=2.2uF
C27 "GRM1555C1H101JA01D" 0402S -225,0 r180 top value=100pF
C28 "GRM1555C1H101JA01D" 0402S -225,-35 r180 top value=100pF
C29 "CGA2B3X7R1E104K050BB" 0402S 130,-125 r180 top value=0.1uF
C30 "T521X336M050ATE050" 7343-43 1650,-425 r270 top value=33uF
C31 "T521X336M050ATE050" 7343-43 1875,-425 r270 top value=33uF
C32 "TR3E106K063C0600" 7343-43 -600,-500 r270 top value=10uF
C33 "C2012X5R2A475K125AC" FP-C2012X5R2A475K125AC_0805-MFG -350,-475 r90 top value=4.7µF
C34 "C2012X5R2A475K125AC" FP-C2012X5R2A475K125AC_0805-MFG -275,-475 r90 top value=4.7µF
C35 "C2012X5R2A475K125AC" FP-C2012X5R2A475K125AC_0805-MFG -200,-475 r90 top value=4.7µF
C36 "C2012X5R2A475K125AC" FP-C2012X5R2A475K125AC_0805-MFG -125,-475 r90 top value=4.7µF
C37 "C2012X5R2A475K125AC" FP-C2012X5R2A475K125AC_0805-MFG -50,-475 r90 top value=4.7µF
C38 "C2012X5R2A475K125AC" FP-C2012X5R2A475K125AC_0805-MFG 25,-475 r90 top value=4.7µF
C39 "C2012X5R2A475K125AC" FP-C2012X5R2A475K125AC_0805-MFG 265,-425 r90 top value=4.7µF
C40 "C2012X5R2A475K125AC" FP-C2012X5R2A475K125AC_0805-MFG 335,-425 r90 top value=4.7µF
C41 "C0603C103J1RACTU" 0603S 400,-425 r270 top value=0.01uF
C42 "GRM155R72A102KA01D" 0402S 445,-425 r270 top value=1000pF
C43 "CGA3E2X7R1H104K080AA" 0603S 125,-550 r0 top value=0.1uF
C44 "C1608X5R1H105K080AB" 0603S 1225,-600 r180 top value=1uF
C45 "CGA3E2X7R1H104K080AA" 0603S 1225,-700 r270 top value=0.1uF
C46 "C3216X7R1V106K160AC" 1206_180 1425,-900 r0 top value=10uF
C47 "T521X336M050ATE050" 7343-43 1925,-1075 r90 top value=33uF
C48 "C3216X7R1V106K160AC" 1206_180 1425,-1000 r0 top value=10uF
C49 "T521X336M050ATE050" 7343-43 2475,275 r90 bottom value=33uF
C50 "T521X336M050ATE050" 7343-43 2250,275 r90 bottom value=33uF
C51 "Capacitor" 0603S 775,500 r90 bottom value=330pF
C52 "HMK107C7224MAHTE" 0603S -50,260 r90 bottom value=0.22uF
C53 "C2012JB1V106K125AC" 0805_HV 2100,200 r90 bottom value=10uF
C54 "C2012JB1V106K125AC" 0805_HV 2000,200 r90 bottom value=10uF
C55 "C2012JB1V106K125AC" 0805_HV 1900,200 r90 bottom value=10uF
C56 "C2012JB1V106K125AC" 0805_HV 1800,200 r90 bottom value=10uF
C57 "C2012JB1V106K125AC" 0805_HV 1700,200 r90 bottom value=10uF
C58 "CGA3E3X7S2A333K080AB" 0603S -210,250 r180 bottom value=0.033uF
C59 "CGA3E3X7S2A333K080AB" 0603S -210,200 r180 bottom value=0.033uF
C60 "Capacitor" 0603S 925,-450 r270 bottom value=330pF
C61 "C2012X7S2A105K125AE" 0805_HV -1525,-150 r180 bottom value=1uF
C62 "Capacitor" 0603S 775,-450 r270 bottom value=330pF
C63 "GRM155R71H183KA12D" 0402S 50,-245 r0 bottom value=0.018uF
C64 "CGA2B3X7R1H683K050BB" 0402S 10,-205 r180 bottom value=0.068uF
C65 "GRM155R71H183KA12D" 0402S -30,-245 r180 bottom value=0.018uF
C66 "T521X336M050ATE050" 7343-43 2000,-425 r270 bottom value=33uF
C67 "T521X336M050ATE050" 7343-43 1775,-425 r270 bottom value=33uF
C68 "T521X336M050ATE050" 7343-43 1525,-425 r270 bottom value=33uF
C69 "GRM1555C1H101JA01D" 0402S -225,-140 r180 top value=100pF
C70 "CGA3E2X7R1H104K080AA" 0603S -1146.39,-305 r180 bottom value=0.1uF
C71 "GRM188R6YA106MA73D" 0603S 945,-1300 r90 bottom value=10uF
C72 "C2012X7S2A105K125AE" 0805_HV 735,-1410 r180 bottom value=1uF
D1 "LED" LED_LTST-C190 -1425,-775 r180 top value=Green
D2 "D3Z5V1BF-7" SOD-323F 35.04,180.04 r180 bottom value=5.1V
D3 "D3Z5V1BF-7" SOD-323F 135,85 r90 bottom value=5.1V
D4 "DFLS2100-7" PowerDI123 300,50 r180 bottom value=100V
D5 "DFLS2100-7" PowerDI123 300,-50 r180 bottom value=100V
D6 "B240A-13-F" SMA 2275,-1100 r90 bottom value=40V
D7 "1N4148WQ-7-F" SOD-123 975,-1075 r0 bottom value=100V
D8 "1N4148WQ-7-F" SOD-123 975,-1175 r0 bottom value=100V
FID1 "Fiducial" Fiducial10-20 -1450,1400 r0 top
FID2 "Fiducial" Fiducial10-20 2450,1400 r0 top
FID3 "Fiducial" Fiducial10-20 2450,-2200 r0 top
FID4 "Fiducial" Fiducial10-20 -1450,1400 r90 bottom
FID5 "Fiducial" Fiducial10-20 2450,-2200 r90 bottom
FID6 "Fiducial" Fiducial10-20 2450,1400 r90 bottom
H3 "Bumpon" Bumpon_SJ5003Transparent -1100,1200 r180 bottom
H4 "Bumpon" Bumpon_SJ5003Transparent 2200,1200 r180 bottom
H5 "Bumpon" Bumpon_SJ5003Transparent 2200,-2000 r180 bottom
H6 "Bumpon" Bumpon_SJ5003Transparent -1100,-2000 r180 bottom
J1 "Receptacle_2x1" On-Shore_ED120_2DS -1450,200 r270 top
J2 "ED120/4DS" On-Shore_ED120_4DS 2450,-300 r90 top
J3 "ED120/4DS" On-Shore_ED120_4DS 2450,-1100 r90 top
J4 "ED555/2DS" TERM_BLK_ED555-2DS -1450,-1400 r270 top
J5 "0022053041" FP-22-05-3041_HDR4-MFG 200,-2378.44 r0 top
J6 "N2510-6002-RB" CONN_2510-6002 1000,-2100 r180 top
JP1 "TSW-102-07-G-S" TSW-102-07-G-S -750,100 r180 top
JP2 "TSW-102-07-G-S" TSW-102-07-G-S -750,-100 r180 top
JP4 "TSW-105-07-G-D" TSW-105-07-G-D -450,-1050 r0 top
L1_A "CMLE104T-3R3MS" FP-CMLE105T-3R3MS-99_SMT_IND_10MM85_10MM0-MFG 850,250 r0 top locked
L1_B "CMLE104T-3R3MS" FP-CMLE105T-3R3MS-99_SMT_IND_10MM85_10MM0-MFG 850,-230.71 r0 top
LBL1 "THT-14-423-10" Label_650x200 650,1275 r0 top
LOGO2 "CAUTION HOT SURFACE" IEC_HotSurface_Small 1425,700 r0 top
Logo3 "WEEE logo" WEEE_Minimum 2450,-1850 r0 top
LOGO4 "CE Mark" CE_Mark_5mm 2050,-2100 r0 top
Logo5 "FCC disclaimer" FCC_disclaimer 430,1515 r0 top
NT1 "Net-Tie" Net-Tie_10milWide_30milLong -100,75 r315 bottom net-tie
Q1_A "" D0133CT44M 350,325 r0 top locked
Q1_B "" D0133CT44M 350,-300 r0 top locked
Q2_A "BSZ070N08LS5" PG-TSDSON-8FL 375,175 r0 top value=80V
Q2_B "BSZ070N08LS5" PG-TSDSON-8FL 375,-150 r0 top value=80V
Q3 "BSC094N06LS5" FP-BSC027N06LS5ATMA1_TDSON8-MFG 1375,375 r90 top locked
Q4 "BSC027N06LS5ATMA1" FP-BSC027N06LS5ATMA1_TDSON8-MFG 1375,125 r270 top locked
Q4_P "BSC027N06LS5ATMA1" FP-BSC027N06LS5ATMA1_TDSON8-MFG 1375,-125 r270 top locked
Q5 "BSC027N06LS5ATMA1" FP-BSC027N06LS5ATMA1_TDSON8-MFG 1375,-400 r0 top locked
Q6 "MOSFET_N_D3G1S2" SOT-23L -1071.39,-850 r90 bottom value=60V
Q7 "MOSFET_N_D3G1S2" SOT-23L -1450,-875 r90 bottom value=60V
Q8 "MOSFET_N_D3G1S2" SOT-23L -875,-1100 r0 bottom value=60V
Q9 "SQJ469EP-T1-GE3" PowerPAK_SO-8L -1021.39,-500 r0 bottom value=-80V
Q10 "NHUMD12X" FP-NHUMD12X_TSSOP6-MFG -1071.39,-700 r180 bottom value=80V
R1 "Resistor" 0603S 100,450 r270 top value=4.99
R2 "Resistor" 0603S 150,450 r270 top value=4.99
R3 "CRCW04021R00JNED" 0402S -25,200 r90 top value=1.0
R4 "5106" 5106 -1109.65,100 r0 top value=0
R5 "CRCW0402200KFKED" 0402S -225,105 r0 top value=200k
R6 "CRCW04021R00JNED" 0402S 155,120 r0 top value=1.0
R7 "CRCW0402300KFKED" 0402S -225,70 r180 top value=300k
R8 "CRCW04023K57FKED" 0402S -225,-70 r0 top value=3.57k
R9 "CRCW040215K0FKED" 0402S -225,-105 r180 top value=15.0k
R10 "RC0402FR-0782KL" 0402S -450,-1200 r90 bottom value=82.0k
R11 "CRCW040210K0FKED" 0402S -170,-225 r90 top value=10.0k
R12 "CRCW040210K0FKED" 0402S -135,-225 r270 top value=10.0k
R13 "CRCW040210K0FKED" 0402S -100,-225 r270 top value=10.0k
R14 "CRCW040210K0FKED" 0402S -65,-225 r270 top value=10.0k
R15 "Resistor" 0603S 100,-450 r90 top value=4.99
R16 "Resistor" 0603S 150,-450 r90 top value=4.99
R17 "Resistor" 0603S 1150,-670 r0 top value=10
R18 "Resistor" 0603S 1150,-730 r0 top value=10
R19 "Resistor" 0603S -1300,-775 r0 top value=2.00k
R21 "Resistor" 0603S 775,600 r270 bottom value=56
R23 "CRCW0402150KFKED" 0402S -550,-1200 r90 bottom value=150k
R24 "CRCW040210K0FKED" 0402S -250,150 r180 bottom value=10.0k
R25 "RC0402FR-07100KL" 0402S -650,-1200 r90 bottom value=100k
R26 "CRCW0402300KFKED" 0402S -950,-1200 r90 bottom value=300k
R27 "Resistor" 0402S -225,110 r0 bottom value=10.0k
R28 "RC0402FR-0733KL" 0402S -350,-1200 r90 bottom value=33.0k
R29 "CRCW04021K00FKED" 0402S -250,-1200 r90 bottom value=1.00k
R30 "Resistor" 0603S 925,-550 r90 bottom value=56
R32 "Resistor" 0603S 775,-550 r90 bottom value=56
R33 "CRCW04022M00JNED" 0402S -70,-205 r0 bottom value=2.0Meg
R34 "Resistor" 1206 -1371.39,-300 r270 bottom value=3.9
R35 "Resistor" 1206 -1496.39,-300 r270 bottom value=3.9
R44 "RC0603FR-07100KL" 0603S -1146.39,-360 r180 bottom value=100k
R45 "CRCW04020000Z0ED" 0402S 1300,-375 r0 bottom value=0
R46 "ERJ-8ENF10R0V" 1206 -1221.39,-600 r90 bottom value=10.0
R47 "CRCW06031R00JNEA" 0603S -1250,225 r270 bottom value=1.0
R48 "CRCW040210K0FKED" 0402S -946.39,-700 r0 bottom value=10.0k
R49 "CRCW080520K0FKEA" 0805_HV -916.39,-765 r180 bottom value=20.0k
R50 "ERJ-8ENF10R0V" 1206 725,-1175 r0 bottom value=10.0
R51 "RC0402JR-13100RL" FP-RC0402JR-13100RL_0402-MFG 350,-2025 r270 bottom value=100
RAC_A "WSLP1206R0100FEA" 1206 125,350 r0 top value=0.01
RAC_B "WSLP1206R0100FEA" 1206 125,-350 r0 top value=0.01
RSR "CSNL2010FT5L00" 2010 1350,-700 r270 top value=0.005
SH-JP1 "SNT-100-BK-G" SNT-100-BK-G -750,100 r180 top value=1x2
SH-JP2 "SNT-100-BK-G" SNT-100-BK-G -755,-100 r180 top value=1x2
SH-JP4 "SNT-100-BK-G" SNT-100-BK-G -350,-1050 r90 top value=1x2
TP1 "5010" Keystone5010 -1100,-1150 r0 top
TP2 "RCU-0C" TE_RCU 340,140 r180 bottom
TP3 "RCU-0C" TE_RCU 240,300 r0 bottom
TP4 "RCU-0C" TE_RCU 170,180 r180 bottom
TP11 "RCU-0C" TE_RCU 250,675 r180 bottom
TP15 "5015" Testpoint_Keystone_Miniature 550,700 r90 top
TP16 "5015" Testpoint_Keystone_Miniature 850,700 r270 top
TP17 "5015" Testpoint_Keystone_Miniature 1150,700 r90 top
TP18 "5011" Keystone5011 -1450,700 r0 top
TP19 "5011" Keystone5011 -850,700 r0 top
TP20 "5011" Keystone5011 1750,700 r0 top
TP21 "5011" Keystone5011 2450,700 r0 top
TP22 "5010" Keystone5010 -850,350 r0 top
TP23 "5010" Keystone5010 1750,-100 r0 top
TP24 "5010" Keystone5010 -1450,-500 r0 top
TP29 "5010" Keystone5010 1175,-900 r0 top
TP30 "5011" Keystone5011 1650,-900 r180 top
TP31 "5010" Keystone5010 1050,-1275 r180 top
TP32 "5010" Keystone5010 -1450,-1150 r0 top
TP33 "5015" Testpoint_Keystone_Miniature 0,-1225 r90 top
TP40 "RCU-0C" TE_RCU 475,675 r180 bottom
TP41 "5011" Keystone5011 -1425,-1825 r0 top
U1 "BQ25770GREER" REE0036A-MFG 0,0 r270 top locked
U2 "TPS7A1633DGNR" DGN0008C_N 775,-1300 r180 bottom
Z1 "SMAJ10A" SMA -1175,-200 r0 bottom value=10V
ZZ1 "This Assembly Note is for PCB labels only" AssemblyNoteLabel 1201.46,6061.5 r0 top
ZZ2 "These assemblies are ESD sensitive, ESD precautions shall be observed." AssemblyNote 1201.46,5961.5 r0 top
ZZ3 "These assemblies must be clean and free from flux and all contaminants. Use of no clean flux is not acceptable." AssemblyNote 1201.46,5861.5 r0 top
ZZ4 "These assemblies must comply with workmanship standards IPC-A-610 Class 2, unless otherwise specified." AssemblyNote 1201.46,5761.5 r0 top

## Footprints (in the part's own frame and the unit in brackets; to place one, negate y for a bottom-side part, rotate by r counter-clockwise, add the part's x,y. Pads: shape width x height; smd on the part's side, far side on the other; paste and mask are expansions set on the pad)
0402S [mil] "Based on C0402S footprint from PADS legacy"
  rect 15x24 smd: 1(-20,0) 2(20,0)
  body extent -22,-12 22,12, height 24
0603S [mil]
  rect 20x35 smd: 1(-30,0) 2(30,0)
  body extent -34,-19 34,19, height 39
0805_HV [mil] "0805 with 30mil clearance between pads"
  rect 50x63 smd: 1(-40,0) 2(40,0)
  silkscreen extent -74,-40 74,40, body extent -43,-29 43,29, height 57
1206 [mm] "1206 from SM-752 data"
  rect 1.3x1.85 smd: 1(-1.45,0) 2(1.45,0)
  silkscreen extent -2.4,-1.21 2.4,1.21, body extent -1.7,-0.9 1.7,0.9, height 1.35
1206_180 [mm] "1206_180"
  rect 1.1x1.6 smd: 1(-1.7,0) 2(1.7,0)
  silkscreen extent -0.9,-1 0.9,1, body extent -1.75,-0.95 1.75,0.95, height 1.8
2010 [mm] "Chip Capacitor, Body 5.08x2.54mm, IPC Medium Density"
  rect 1.6x2.7 smd: 1(-2.3,0) 2(2.3,0)
  silkscreen extent -3.42,-1.65 3.42,1.65, body extent -2.73,-1.45 2.73,1.45, height 1.66
5106 [mm] "Keystone"
  rect 0.99x1.4 smd: 1(-0.85,0) 2(0.88,0)
  silkscreen extent -1.63,-0.97 1.65,0.97, body extent -1.06,-0.69 1.06,0.69, height 0.84
7343-43 [mm] "Medium density IPC based on Kemet T495 series"
  rect 2.55x2.45 smd: 1(-3.025,0) 2(3.025,0)
  silkscreen extent -4.56,-2.3 3.8,2.3, body extent -3.8,-2.3 3.8,2.3, height 4.3
AssemblyNote [mil] "Assembly Note"
AssemblyNoteLabel [mil] "Assembly Note for PCB Labels"
Bumpon_SJ5003Transparent [mil] "3M Hemispherical Bumpon transparent"
  round 1 on Mech4: 0(0,0)
  silkscreen extent -228,-228 228,228, body extent -219,-219 219,219, height 197
CE_Mark_5mm [mil] "Minimum text height for CE Mark"
  silkscreen extent -138,-98 138,98
CONN_2510-6002 [mm] "3M 2500 series TS-0770-L December 15, 2011"
  rect 1.65x1.65 hole 1.016 mask+0: 1(-5.08,-1.27)
  round 1.65 hole 1.016 mask+0: 2(-5.08,1.27) 3(-2.54,-1.27) 4(-2.54,1.27) 5(0,-1.27) 6(0,1.27) 7(2.54,-1.27) 8(2.54,1.27) 9(5.08,-1.27) 10(5.08,1.27)
  silkscreen extent -10.01,-4.17 10.01,4.47, body extent -10.01,-4.11 10.01,4.52, height 9.92
D0133CT44M [mm] "EPC2055/EPC2204"
  rrect30% 0.301x0.351 smd paste-0.2 mask-0.2: 1(-1,0.525)
  rrect30% 0.301x0.876 smd paste-0.2 mask-0.2: 2(-1,-0.262)
  rrect30% 0.301x1.226 smd paste-0.2 mask-0.2: 3(-0.5,0) 5(0.5,0)
  rrect30% 0.301x1.401 smd paste-0.2 mask-0.2: 4(0,0) 6(1,0)
  rrect50% 0.23x0.805 on Top Solder mask-0.2: ""(-1,-0.262)
  rrect50% 0.23x0.28 on Top Solder mask-0.2: ""(-1,0.525)
  rrect50% 0.23x0.805 on Top Paste mask-0.2: ""(-1,-0.261)
  rrect50% 0.23x0.28 on Top Paste mask-0.2: ""(-1,0.526)
  rrect50% 0.23x1.155 on Top Solder mask-0.2: ""(-0.5,0) ""(0.5,0)
  rrect50% 0.21x1.155 on Top Paste mask-0.2: ""(-0.5,0.001) ""(0.5,0.001)
  rrect50% 0.23x1.33 on Top Solder mask-0.2: ""(0,0) ""(1,0)
  rrect50% 0.21x1.33 on Top Paste mask-0.2: ""(0,0.001) ""(1,0.001)
  silkscreen extent -1.38,-0.87 1.38,0.91, body extent -1.25,-0.75 1.25,0.75, height 0.65
DGN0008C_N [mm] "TSOP, 8-Leads, Body 3x3mm, Pitch 0.65mm, Thermal Pad 1.98x1.88mm, IPC Medium Density"
  rrect22% 1.35x0.45 smd: 1(-2.225,0.975) 2(-2.225,0.325) 3(-2.225,-0.325) 4(-2.225,-0.975) 5(2.225,-0.975) 6(2.225,-0.325) 7(2.225,0.325) 8(2.225,0.975)
  rrect6% 1.6x1.92 on Bottom Paste: 9(0,0)
  rrect10% 2x3 smd paste-2 mask-2: 9(0,0)
  rrect6% 1.6x1.92 on Bottom Solder: 9(0,0)
  silkscreen extent -2.65,-1.55 0.95,1.55, body extent -2.45,-1.5 2.45,1.5, height 1.1
FCC_disclaimer [mil]
Fiducial10-20 [mm]
  round 1 smd mask+0.5: 1(0,0)
  Top Layer keep-out circle w1.178: c0,0 r0.5
FP-22-05-3041_HDR4-MFG [mm]
  rrect6% 1.57x1.57 hole 1.02 paste-2539.97 mask+0: 1(-3.81,7.073)
  round 1.57 hole 1.02 paste-2539.97 mask+0: 2(-1.27,7.073) 3(1.27,7.073) 4(3.81,7.073)
  silkscreen extent -6.13,1.03 5.08,6.44, body extent -5.18,-6.28 5.18,7.96, height 0.25
FP-BSC027N06LS5ATMA1_TDSON8-MFG [mm]
  rrect20% 0.5x0.85 smd paste-1000 mask+0: 1(-1.905,-2.9) 2(-0.635,-2.9) 3(0.635,-2.9) 4(1.905,-2.9)
  rrect2% 4.41x4.55 smd paste-1000 mask-1000: 5-6-7-8(0,1.05)
  silkscreen extent -2.68,-4.08 2.68,3.05, body extent -3,-3.42 3,3.42, height 0.25
FP-C2012X5R2A475K125AC_0805-MFG [mm]
  rrect13% 0.8x1.05 smd paste+0 mask+0: 1(-0.925,0) 2(0.925,0)
  silkscreen extent -0.15,-0.75 0.15,0.75, body extent -1,-0.63 1,0.63, height 1.5
FP-CMLE105T-3R3MS-99_SMT_IND_10MM85_10MM0-MFG [mm]
  rrect2% 4.1x4.1 smd paste+0 mask+0: 1(-4.75,0) 2(4.75,0)
  silkscreen extent -5.6,-5.15 5.6,5.15, body extent -5.42,-5 5.43,5, height 5
FP-NHUMD12X_TSSOP6-MFG [mm]
  rrect17% 0.6x0.6 smd paste-1000 mask+0: 1(-0.9,0.75) 3(-0.9,-0.75) 4(0.9,-0.75) 6(0.9,0.75)
  rrect25% 0.6x0.4 smd paste+0 mask+0: 2(-0.9,0) 5(0.9,0)
  silkscreen extent -1.9,-1.1 0.15,1.1, body extent -1.05,-1 1.05,1, height 1.1
FP-RC0402JR-13100RL_0402-MFG [mm]
  rrect20% 0.5x0.6 smd paste+0 mask+0: 1(-0.5,0) 2(0.5,0)
  silkscreen extent -0.5,-0.67 0.5,0.67, body extent -0.5,-0.25 0.5,0.25, height 0.4
IEC_HotSurface_Small [mil]
  silkscreen extent -107,-93 107,92
Keystone5010 [mil] "Keystone Multipurpose loops"
  round 87 hole 63: 1(0,0)
  silkscreen extent -70,-70 70,70, body extent -63,-63 63,62, height 319
Keystone5011 [mil] "Keystone Multipurpose loops"
  round 87 hole 63: 1(0,0)
  silkscreen extent -70,-70 70,70, body extent -63,-63 63,62, height 319
Label_650x200 [mil] "Thermal Transfer Label"
  round 1 on Mech13: 0(0,0)
  silkscreen extent -325,-100 325,100, body extent -325,-100 325,100, height 1
LED_LTST-C190 [mm] "Lite-On"
  rect 0.8x0.8 smd: 1(-0.75,0) 2(0.75,0)
  silkscreen extent -1.1,-0.8 1.8,0.8, body extent -0.85,-0.45 0.85,0.45, height 0.9
Net-Tie_10milWide_30milLong [mil] "10mil net tie, no solder mask opening, no solder paste"
  rect 30x10 smd paste-5 mask-5: 1(-15,0) 2(15,0)
On-Shore_ED120_2DS [mm] "ONSHORE"
  rrect5% 2x2 hole 1.25: 1(-2.54,0)
  round 2 hole 1.25: 2(2.54,0)
  silkscreen extent -5.6,-4 5.12,5, body extent -5.78,-4 5.08,5, height 13
On-Shore_ED120_4DS [mm] "ONSHORE"
  rrect5% 2x2 hole 1.25: 1(-7.62,0)
  round 2 hole 1.25: 2(-2.54,0) 3(2.54,0) 4(7.62,0)
  silkscreen extent -10.68,-4 10.16,5, body extent -10.86,-4 10.16,5, height 13
PG-TSDSON-8FL [mm] "SMD, 8-Leads, Body 3.3x3.3mm, Pitch 0.65mm"
  rect 1x0.34 smd: 1(-1.45,0.975) 2(-1.45,0.325) 3(-1.45,-0.325) 4(-1.45,-0.975)
  rect 0.8x0.34 smd: 5(1.55,-0.975) 6(1.55,-0.325) 7(1.55,0.325) 8(1.55,0.975)
  rect 0.5x0.5 smd: 9(0,0)
  Top Layer region: -0.56,-1.145 1.15,-1.145 1.15,1.145 -0.56,1.145
  Top Layer region: -0.95,1.15 -1.45,1.15 -1.45,-0.49 -0.95,-0.49
  silkscreen extent -2.22,-1.8 2.22,1.8, body extent -1.7,-1.7 1.7,1.7, height 1.11
PowerDI123 [mm] "Diodes Inc recommended land pattern, document number DS30628 Rev. 6-2"
  rect 2.2x1.4 smd: 1(-1.275,0)
  rect 0.9x1.4 smd: 2(1.275,0)
  silkscreen extent -3.1,-1.09 1.76,1.09, body extent -2.37,-0.96 1.53,0.97, height 1
PowerPAK_SO-8L [mm] "based on Vishay recommended land pattern Document 63818 Feb 7, 2012"
  rect 1x0.41 smd: 1(-2.805,1.905) 2(-2.805,0.635) 3(-2.805,-0.635) 4(-2.805,-1.905)
  rect 3.63x4.061 smd: 5(0.805,0)
  Top Layer region: -0.298,-2.03 0.297,-2.03 0.297,-2.64 -0.298,-2.64
  Top Layer region: -0.298,2.64 0.297,2.64 0.297,2.03 -0.298,2.03
  Top Layer region: 2.615,2.5 3.125,2.5 3.125,-2.5 2.615,-2.5
  body extent -3.07,-2.57 3.08,2.57, height 1.21
REE0036A-MFG [mm]
  rrect50% 0.6x0.2 smd paste+0 mask+0: 1(-1.9,1.8) 2(-1.9,1.4) 3(-1.9,1) 4(-1.9,0.6) 5(-1.9,0.2) 6(-1.9,-0.2) 7(-1.9,-0.6) 8(-1.9,-1) 9(-1.9,-1.4) 10(-1.9,-1.8) 19(1.9,-1.8) 20(1.9,-1.4) 21(1.9,-1) 22(1.9,-0.6) 23(1.9,-0.2) 24(1.9,0.2) 25(1.9,0.6) 26(1.9,1) 27(1.9,1.4) 28(1.9,1.8)
  rrect50% 0.2x0.6 smd paste+0 mask+0: 11(-1.4,-2.4) 12(-1,-2.4) 13(-0.6,-2.4) 14(-0.2,-2.4) 15(0.2,-2.4) 16(0.6,-2.4) 17(1,-2.4) 18(1.4,-2.4) 29(1.4,2.4) 30(1,2.4) 31(0.6,2.4) 32(0.2,2.4) 33(-0.2,2.4) 34(-0.6,2.4) 35(-1,2.4) 36(-1.4,2.4)
  rrect7% 2.7x3.7 smd paste-1000 mask+0: 37(0,0)
  silkscreen extent -2.87,-2.55 2.05,2.55, body extent -2.3,-2.8 2.3,2.8, height 0.25
SMA [mm] "Molded Diode, 2-Leads, Body 4.3x2.6mm, IPC Medium Density, based on OnSemi component dimensions and land pattern"
  rect 2x2 smd: 1(-2,0) 2(2,0)
  silkscreen extent -3.66,-1.57 2.79,1.57, body extent -2.6,-1.3 2.6,1.3, height 2.42
SNT-100-BK-G [mil] "Samtec STEP model"
  round 1 on Mech3: 0(0,0)
  body extent -100,-50 100,50, height 344
SOD-123 [mm] "On Semi recommended land pattern"
  rect 0.915x1.22 smd: 1(-1.637,0) 2(1.637,0)
  silkscreen extent -2.74,-1.17 2.03,1.17, body extent -1.93,-0.9 1.93,0.9, height 1.35
SOD-323F [mm] "NXP recommended land pattern"
  rect 0.6x0.6 smd paste-0.05: 1(-1.1,0) 2(1.1,0)
  silkscreen extent -2.06,-0.86 1.53,0.86, body extent -1.35,-0.67 1.35,0.67, height 0.79
SOT-23L [mm] "SOT23, 3-Leads, Body 2.9x1.3mm, Pitch 0.95mm, Lead Span 2.5mm, IPC High Density"
  rrect50% 0.8x0.6 smd: 1(-1.1,0.95) 2(-1.1,-0.95) 3(1.1,0)
  silkscreen extent -1.5,-1.5 0.7,1.5, body extent -1.16,-1.45 1.21,1.45, height 1
TE_RCU [mm] "SMD, 1-Leads, Body 1.6x0.8mm"
  rrect8% 2.4x1.2 smd: 1(0,0)
  body extent -0.8,-0.45 0.8,0.45, height 1.15
TERM_BLK_ED555-2DS [mil]
  rrect4% 100x100 hole 50: 1(0,0)
  round 100 hole 50: 2(138,0)
  silkscreen extent -93,-161 215,113, body extent -69,-150 207,106, height 323
Testpoint_Keystone_Miniature [mil] "Miniature SMT test point"
  rect 135x70 smd: 1(0,0)
  silkscreen extent -78,-46 78,45, body extent -52,-20 52,20, height 61
TSW-102-07-G-S [mm] "Samtec 100mil, 1x2, 230 mil above insulator"
  rrect50% 1.65x1.65 hole 1.016: 1(-1.27,0)
  round 1.65 hole 1.016: 2(1.27,0)
  silkscreen extent -3.17,-1.27 2.54,1.27, body extent -2.54,-1.27 2.54,1.27, height 8.38
TSW-105-07-G-D [mm] "Samtec 100mil, 2x5, 230 mil above insulator"
  rrect6% 1.65x1.65 hole 1.016: 1(-5.08,-1.27)
  round 1.65 hole 1.016: 2(-5.08,1.27) 3(-2.54,-1.27) 4(-2.54,1.27) 5(0,-1.27) 6(0,1.27) 7(2.54,-1.27) 8(2.54,1.27) 9(5.08,-1.27) 10(5.08,1.27)
  silkscreen extent -7.37,-2.54 6.35,2.54, body extent -6.35,-2.54 6.35,2.54, height 8.38
WEEE_Minimum [mil] "WEEElie bin"
  silkscreen extent -95,-172 99,104

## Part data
C1 C32: library part CMP-0011990-2, "CAP, TA, 10 uF, 63 V, +/- 10%, 0.6 ohm, SMD", Manufacturer=Vishay-Sprague, Supplier Part Number 1=718-1714-1-ND, Tolerance_%=10%, Value1="0.6 ohm", Value2=63V, ValueDisplayed=10uF
C2 C43 C45 C70: library part CMP-0007078-4, "CAP, CERM, 0.1 uF, 50 V, +/- 10%, X7R, AEC-Q200 Grade 1, 0603", Cap_Case=0603, Manufacturer=TDK, Supplier Part Number 1=445-5666-1-ND, TempCo=X7R, Tolerance_%=10%, Value1="0.0296 ohm", Value2=50V, ValueDisplayed=0.1uF
C3 C4 C5 C6 C7 C8 C9 C10 C33 C34 C35 C36 C37 C38 C39 C40: library part CMP-0098058-1, "4.7 µF ±10% 100V Ceramic Capacitor X5R 0805 (2012 Metric)", Digikey Part Number=445-C2012X5R2A475K125ACCT-ND, Manufacturer=TDK, Mouser Part Number=810-C2012X5R2A475K12, Operating Temperature Range="-55°C to +85°C", TempCo=15%, Temperature Characteristic=X5R, Tolerance_%=10%, ValueDisplayed=4.7uF
C11 C21 C41: library part CMP-0006848-4, "CAP, CERM, 0.01 uF, 100 V, +/- 5%, X7R, 0603", Cap_Case=0603, Manufacturer=Kemet, Supplier Part Number 1=399-3190-1-ND, TempCo=X7R, Tolerance_%=5%, Value1=Unknown, Value2=100V, ValueDisplayed=0.01uF
C12 C42: library part CMP-0006699-2, "CAP, CERM, 1000 pF, 100 V, +/- 10%, X7R, 0402", Cap_Case=0402, Manufacturer=MuRata, Supplier Part Number 1=GRM155R72A102KA01D-ND, TempCo=X7R, Tolerance_%=10%, Value1=Unknown, Value2=100V, ValueDisplayed=1000pF
C13 C30 C31 C47 C49 C50 C66 C67 C68: library part CMP-0012653-3, "CAP, Tantalum Polymer, 33 uF, 50 V, +/- 20%, 0.05 ohm, 7343-43 SMD", Cap_Case=7.3x4.3x4.3mm, Manufacturer=Kemet, Supplier Part Number 1=01AC5423, Tolerance_%=20%, Value1="0.05 ohm", Value2=50V, ValueDisplayed=33uF
C14 C15 C16 C17 C18 C53 C54 C55 C56 C57: library part CMP-0085894-1, "CAP, CERM, 10 µF, 50 V,+/- 10%, JB, 0805", Cap_Case=0805, Manufacturer=muRata, PartNumber=GRM21BR61H106KE43L, TempCo=JB, Tolerance_%=10%, Value2=50V, ValueDisplayed=10µF
C19 C22 C58 C59: library part CMP-0007100-4, "CAP, CERM, 0.033 uF, 100 V, +/- 10%, X7S, AEC-Q200 Grade 1, 0603", Cap_Case=0603, Manufacturer=TDK, Supplier Part Number 1=445-6935-1-ND, TempCo=X7S, Tolerance_%=10%, Value1="0.139637 ohm", Value2=100V, ValueDisplayed=0.033uF
C20 C24 C29: library part CMP-0080610-1, "CAP, CERM, 0.1 µF, 25 V,+/- 10%, X7R, AEC-Q200 Grade 1, 0402", Cap_Case=0402, Manufacturer=TDK, Supplier Part Number 1=445-6902-1-ND, TempCo=X7R, Tolerance_%=10%, Value2=25V, ValueDisplayed=0.1µF
C23 C26: library part CMP-0081010-1, "CAP, CERM, 2.2 µF, 25 V,+/- 20%, X5R, 0402", Cap_Case=0402, Manufacturer=MuRata, Supplier Part Number 1=490-10457-1-ND, TempCo=X5R, Tolerance_%=20%, Value2=25V, ValueDisplayed=2.2µF
C25 C27 C28 C69: library part CMP-0006410-2, "CAP, CERM, 100 pF, 50 V, +/- 5%, C0G/NP0, 0402", Cap_Case=0402, Manufacturer=MuRata, Supplier Part Number 1=81-GRM1555C1H101JA1D, TempCo=C0G/NP0, Tolerance_%=5%, Value1=Unknown, Value2=50V, ValueDisplayed=100pF
C44: library part CMP-0007011-5, "CAP, CERM, 1 uF, 50 V, +/- 10%, X5R, 0603", Cap_Case=0603, Manufacturer=TDK, Supplier Part Number 1=445-7468-1-ND, TempCo=X5R, Tolerance_%=10%, Value1="0.005522 ohm", Value2=50V, ValueDisplayed=1uF
C46 C48: library part CMP-0008705-2, "CAP, CERM, 10 uF, 35 V, +/- 10%, X7R, 1206", Cap_Case=1206_180, Manufacturer=TDK, Supplier Part Number 1=445-14799-1-ND, TempCo=X7R, Tolerance_%=10%, Value1="0.002229 ohm", Value2=35V, ValueDisplayed=10uF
